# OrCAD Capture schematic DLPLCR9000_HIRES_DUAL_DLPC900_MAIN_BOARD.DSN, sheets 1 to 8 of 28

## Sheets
1 P02-Import Notice
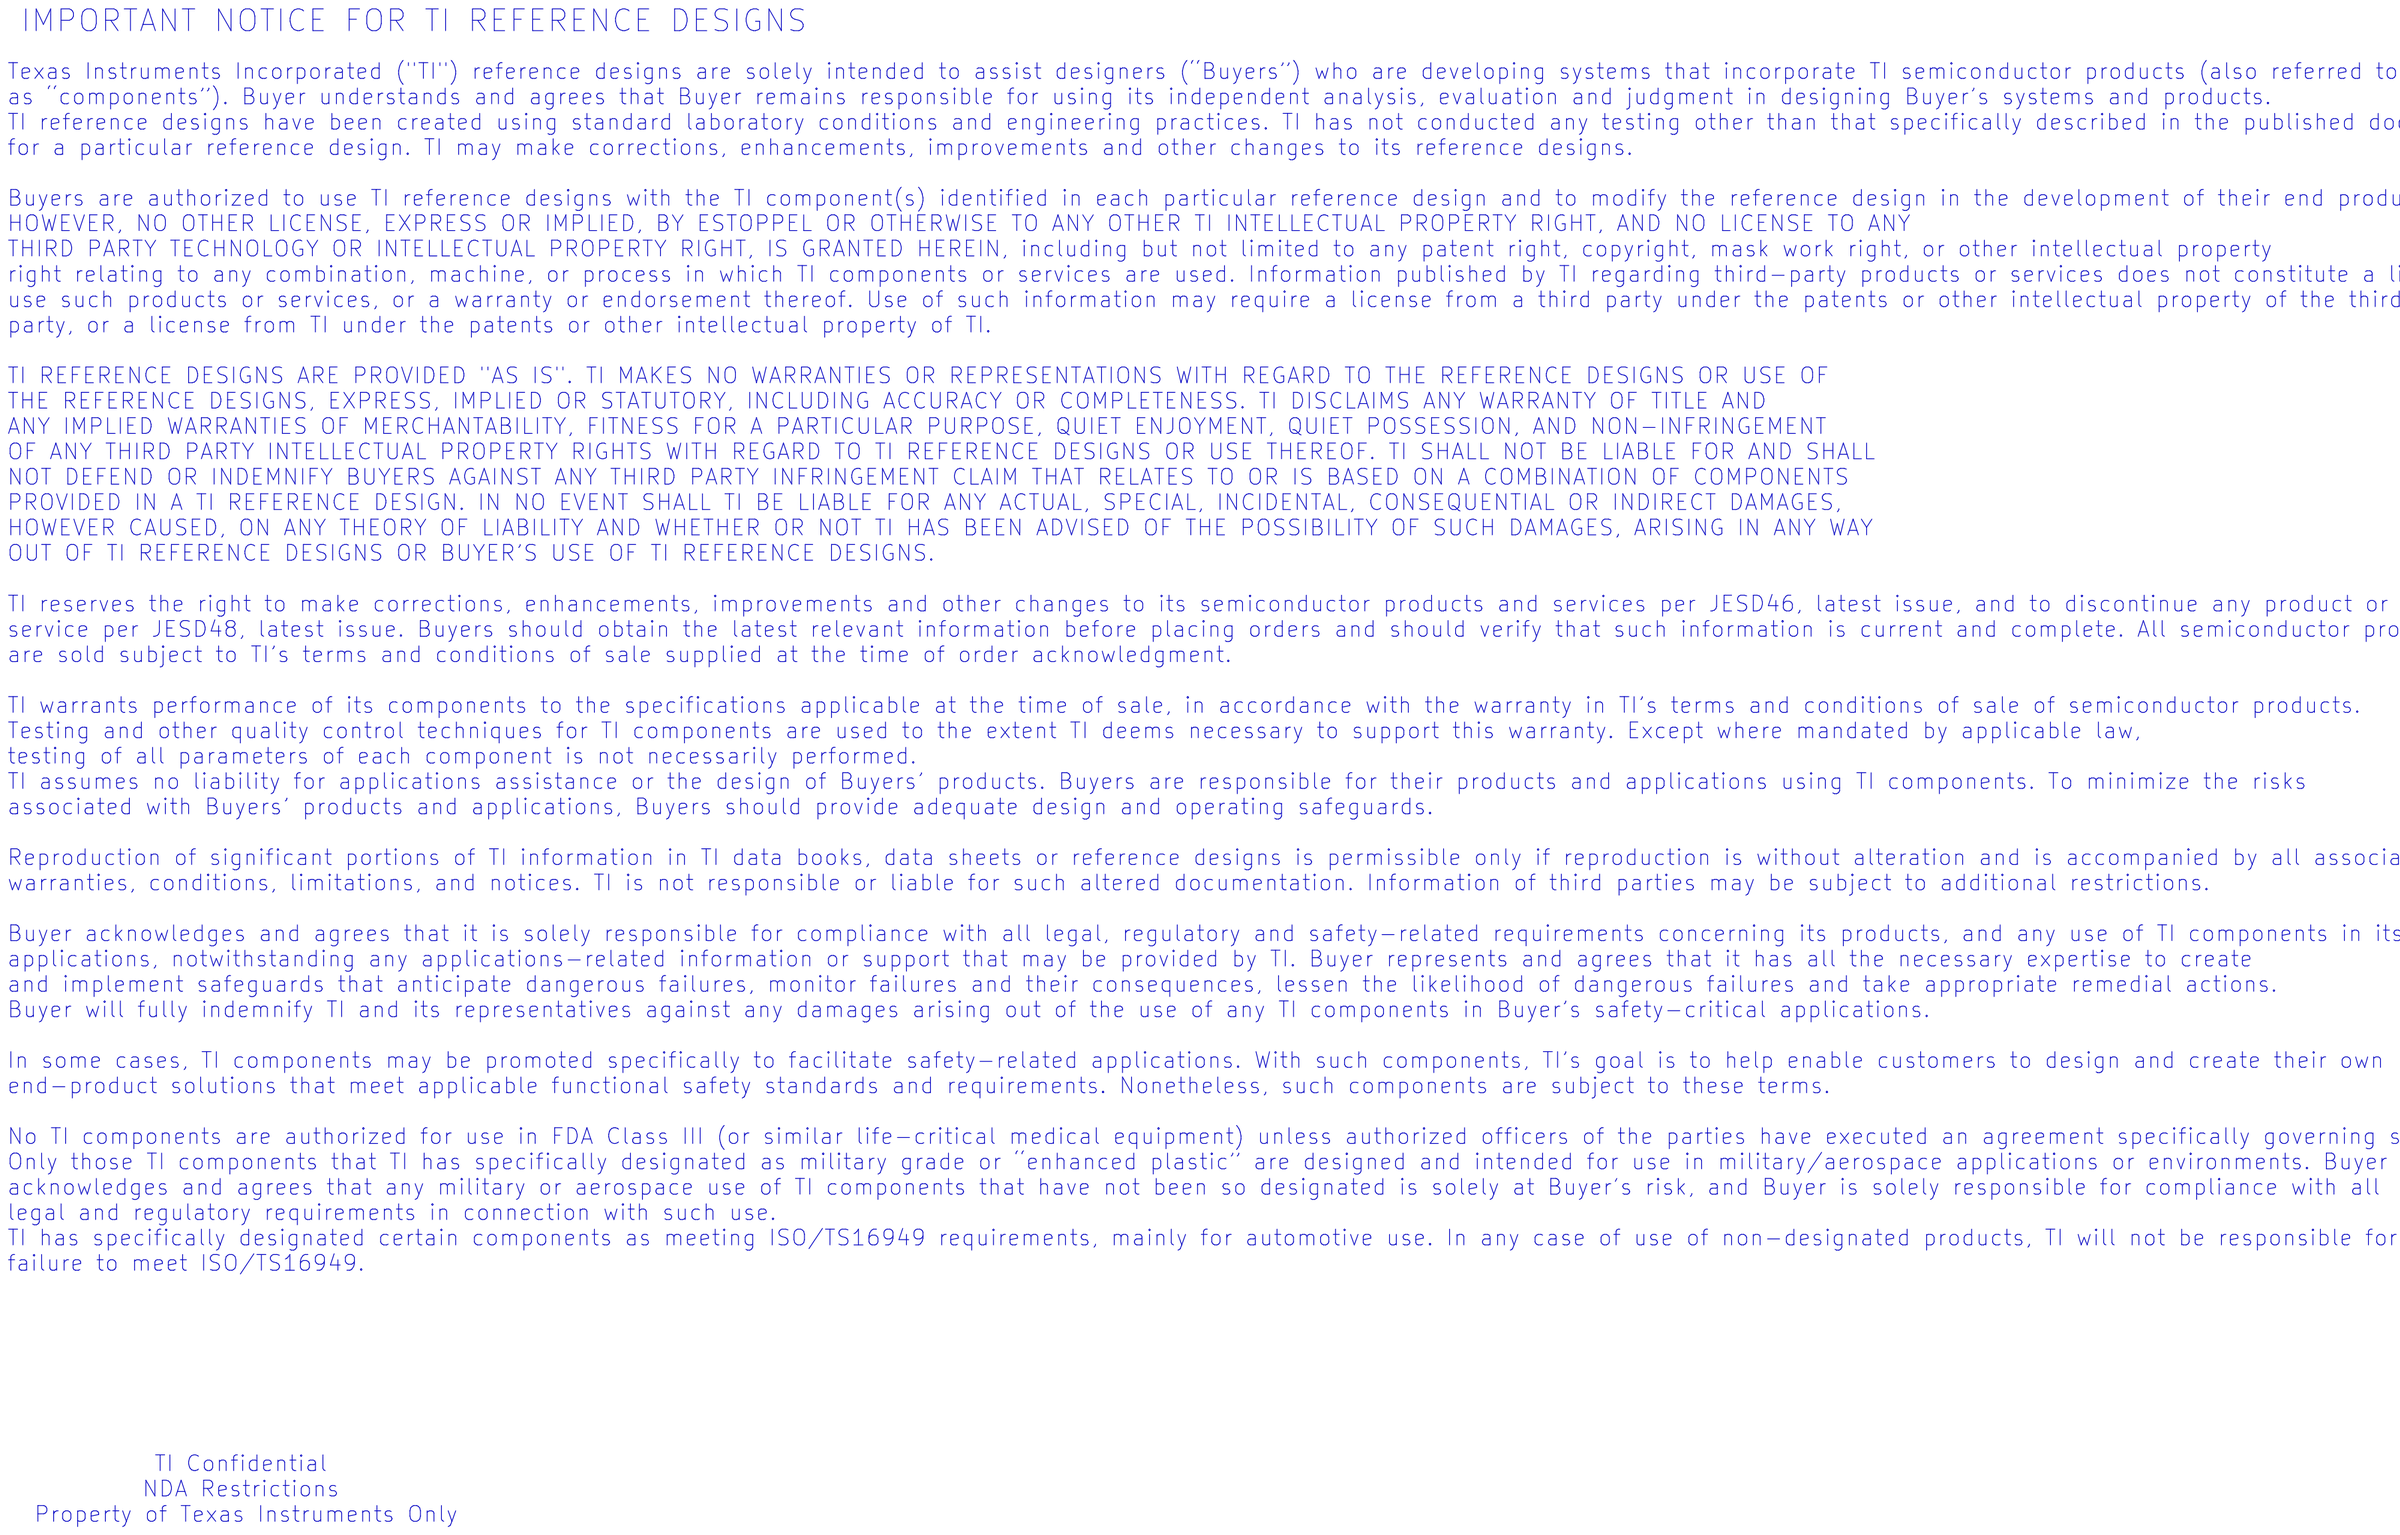
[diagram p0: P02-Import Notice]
2 P25-Power VCCIO & LDO: size A3
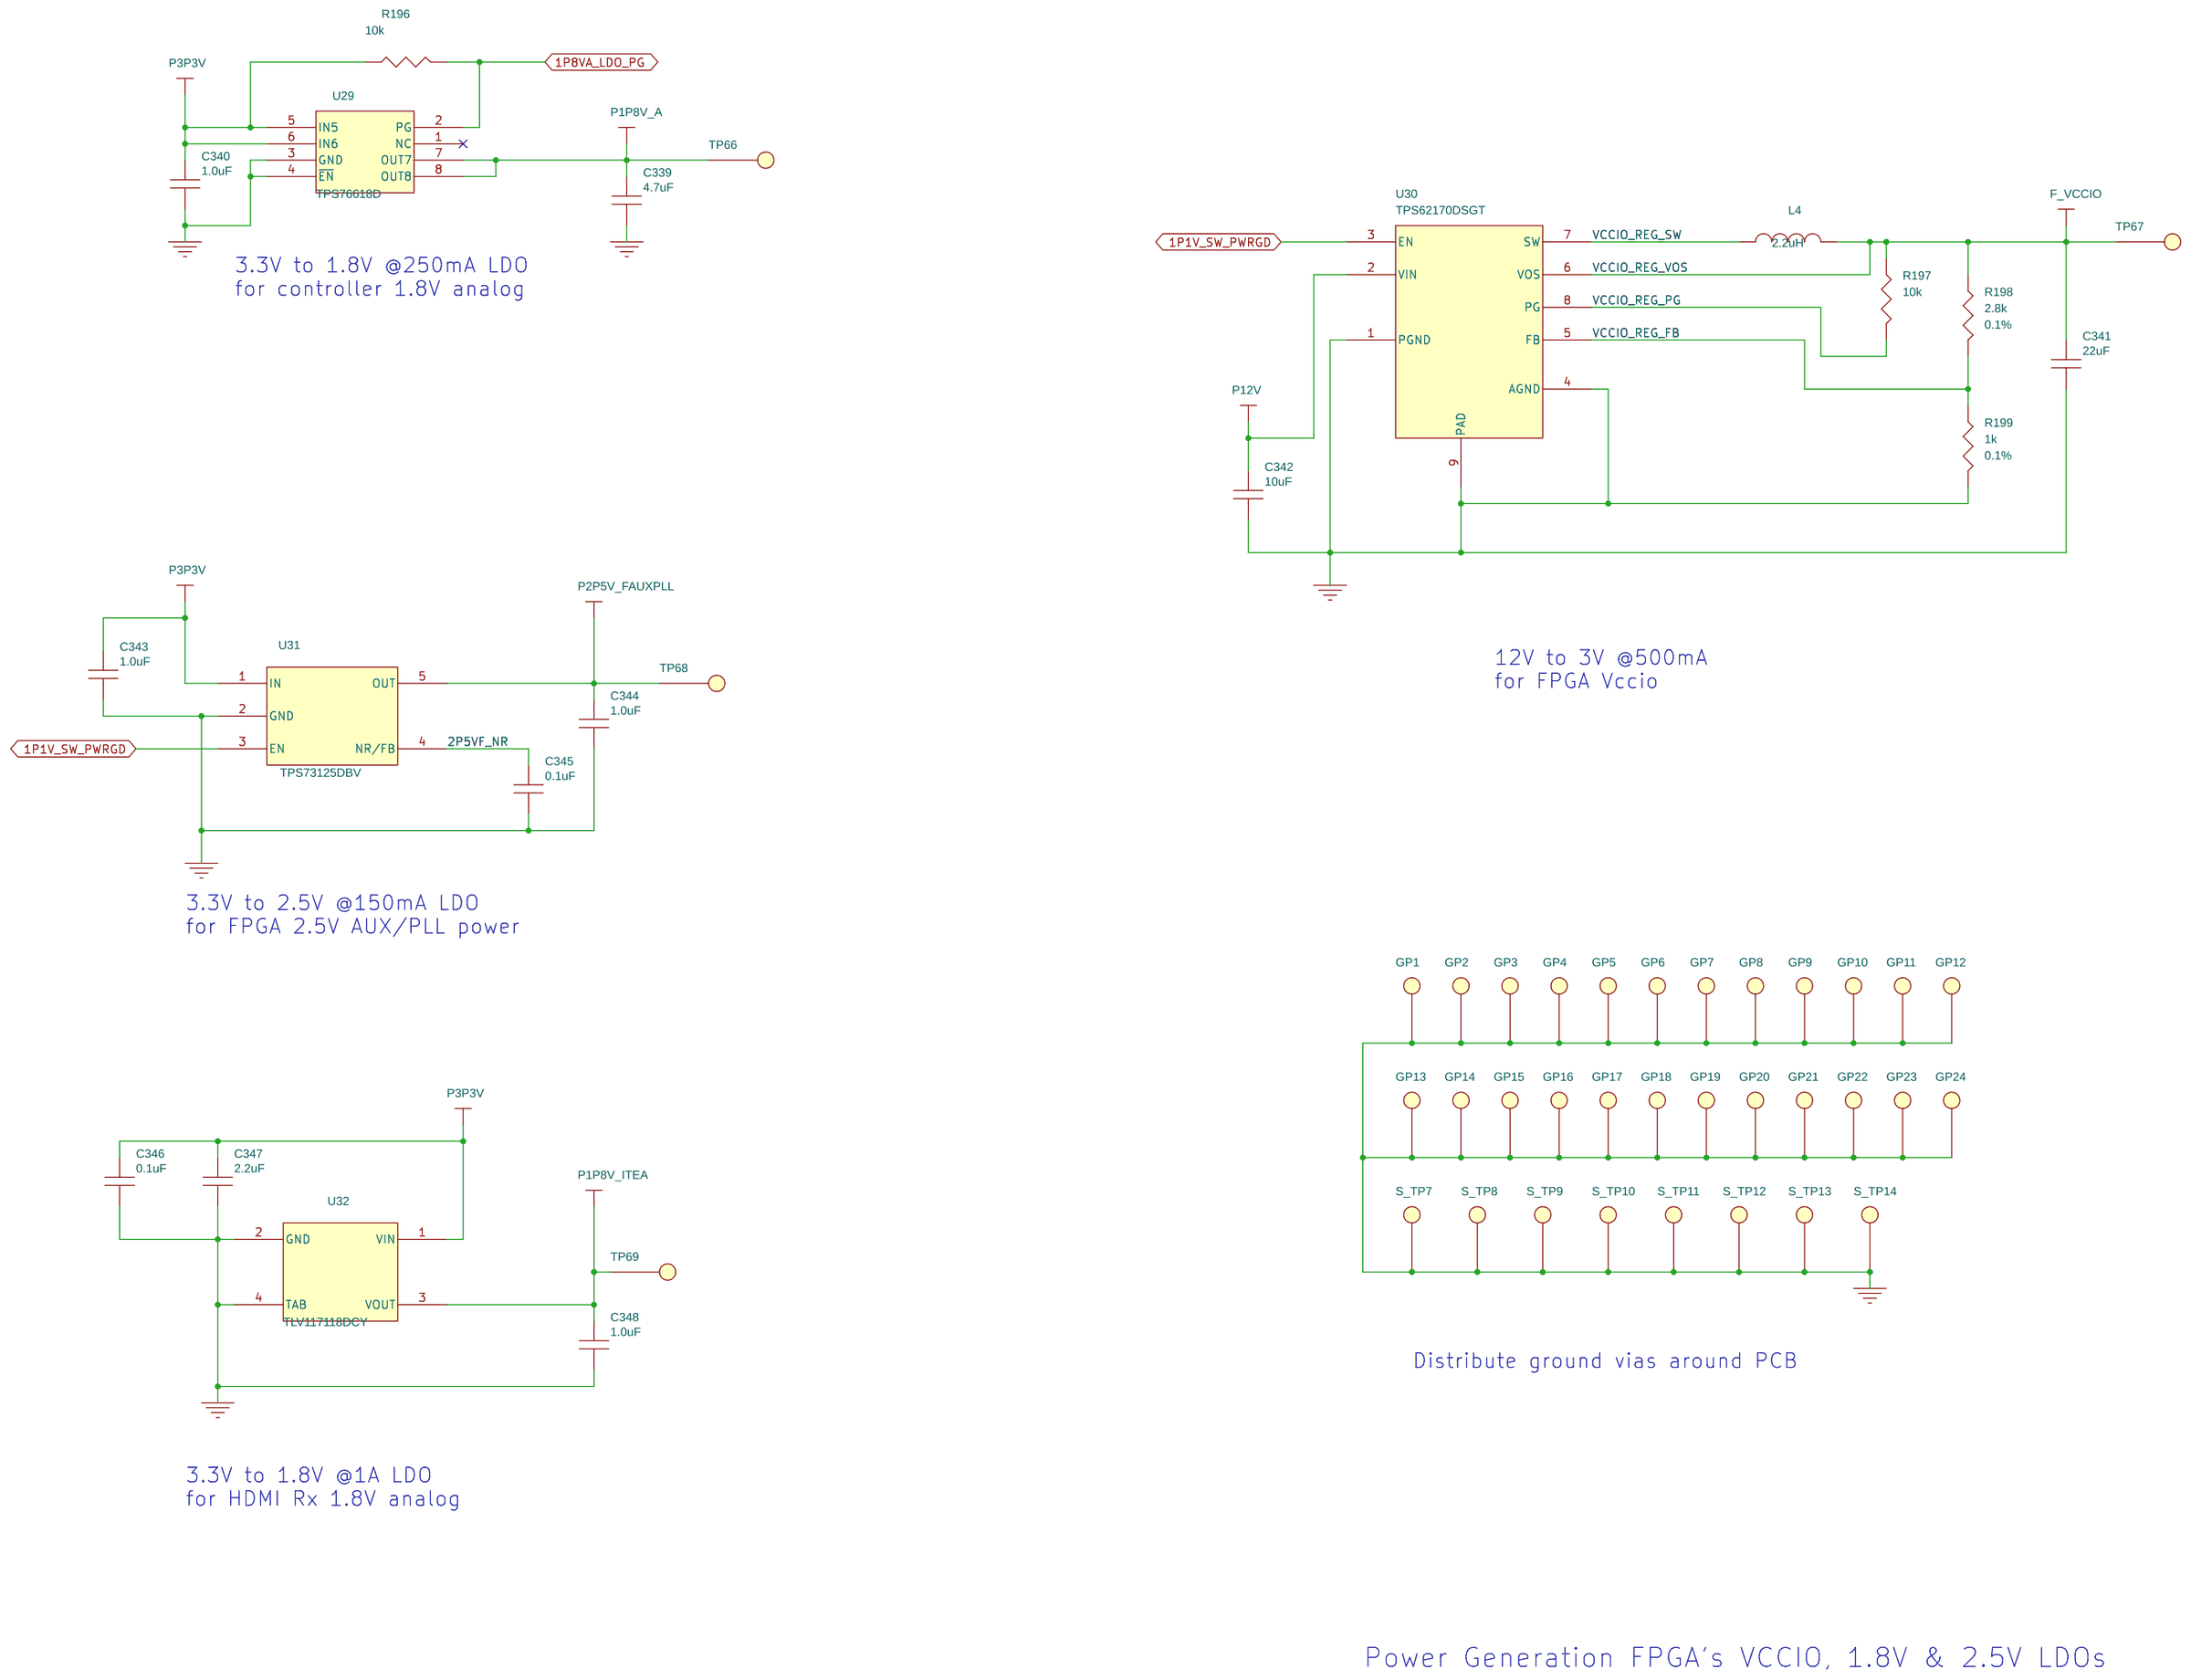
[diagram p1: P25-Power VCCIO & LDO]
3 P10-FPGA Config: size A3
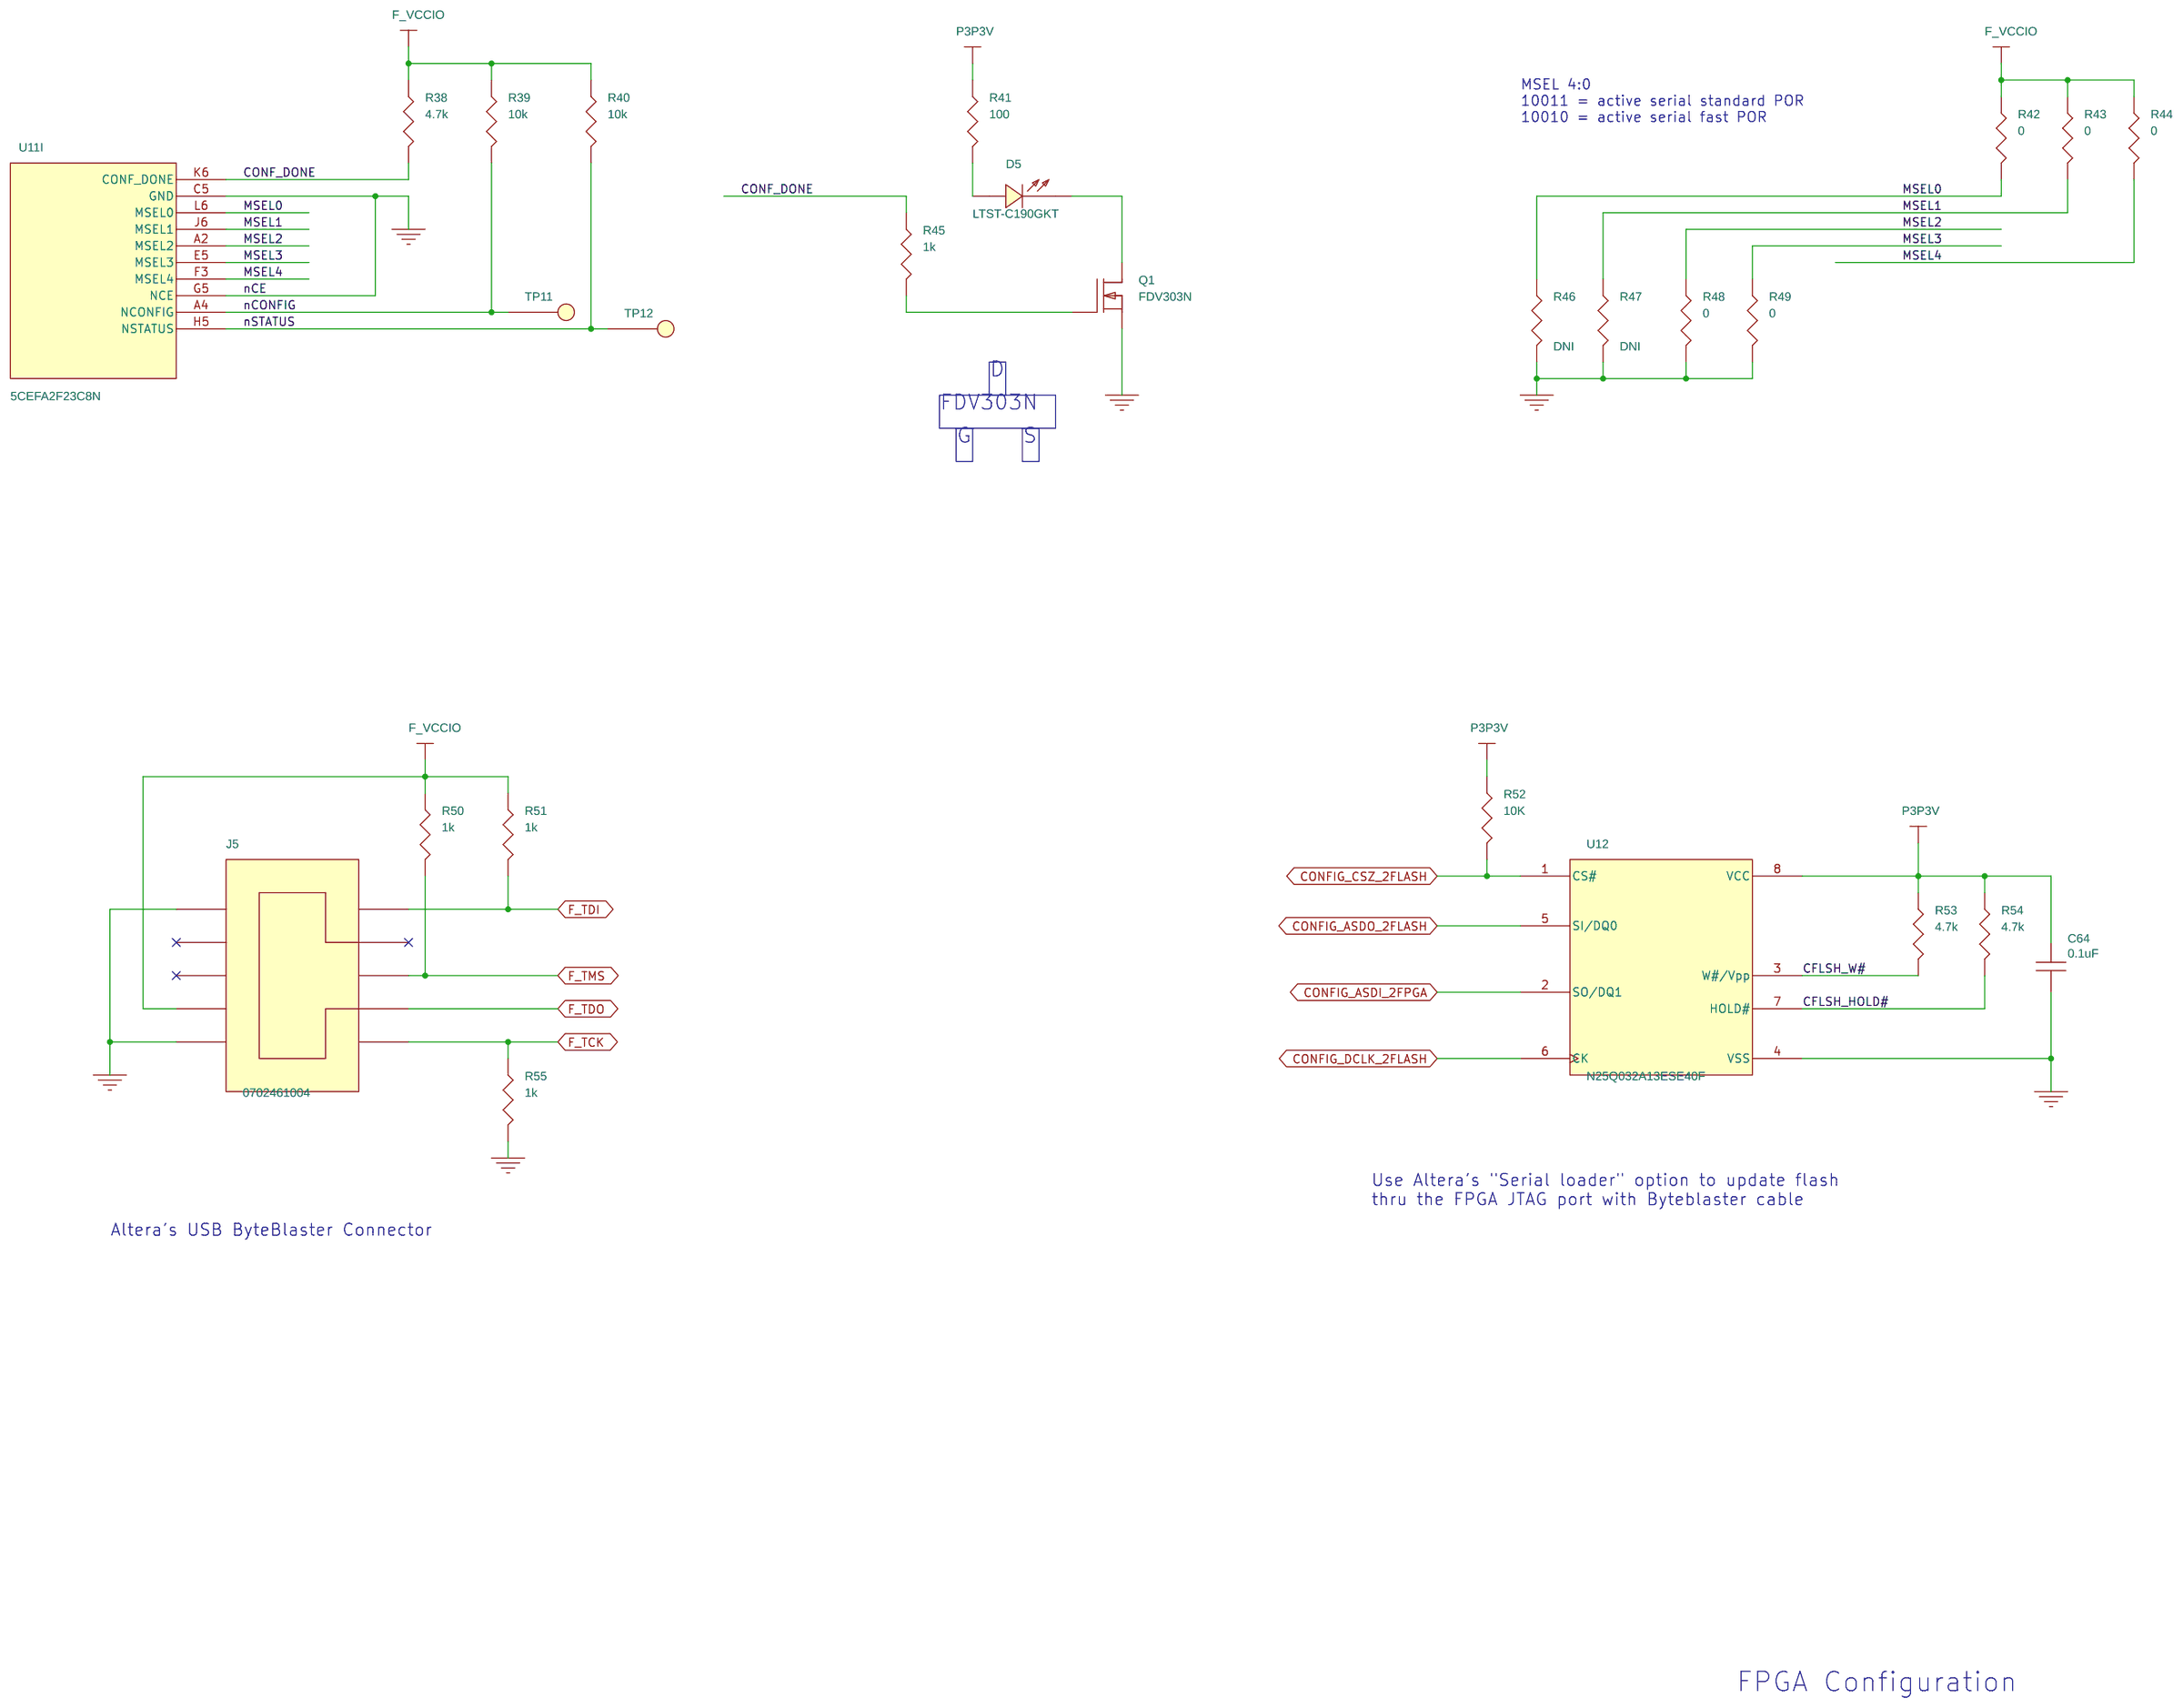
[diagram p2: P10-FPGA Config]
4 P09-FPGA Bank 5A,5B,7A,8A: size A3
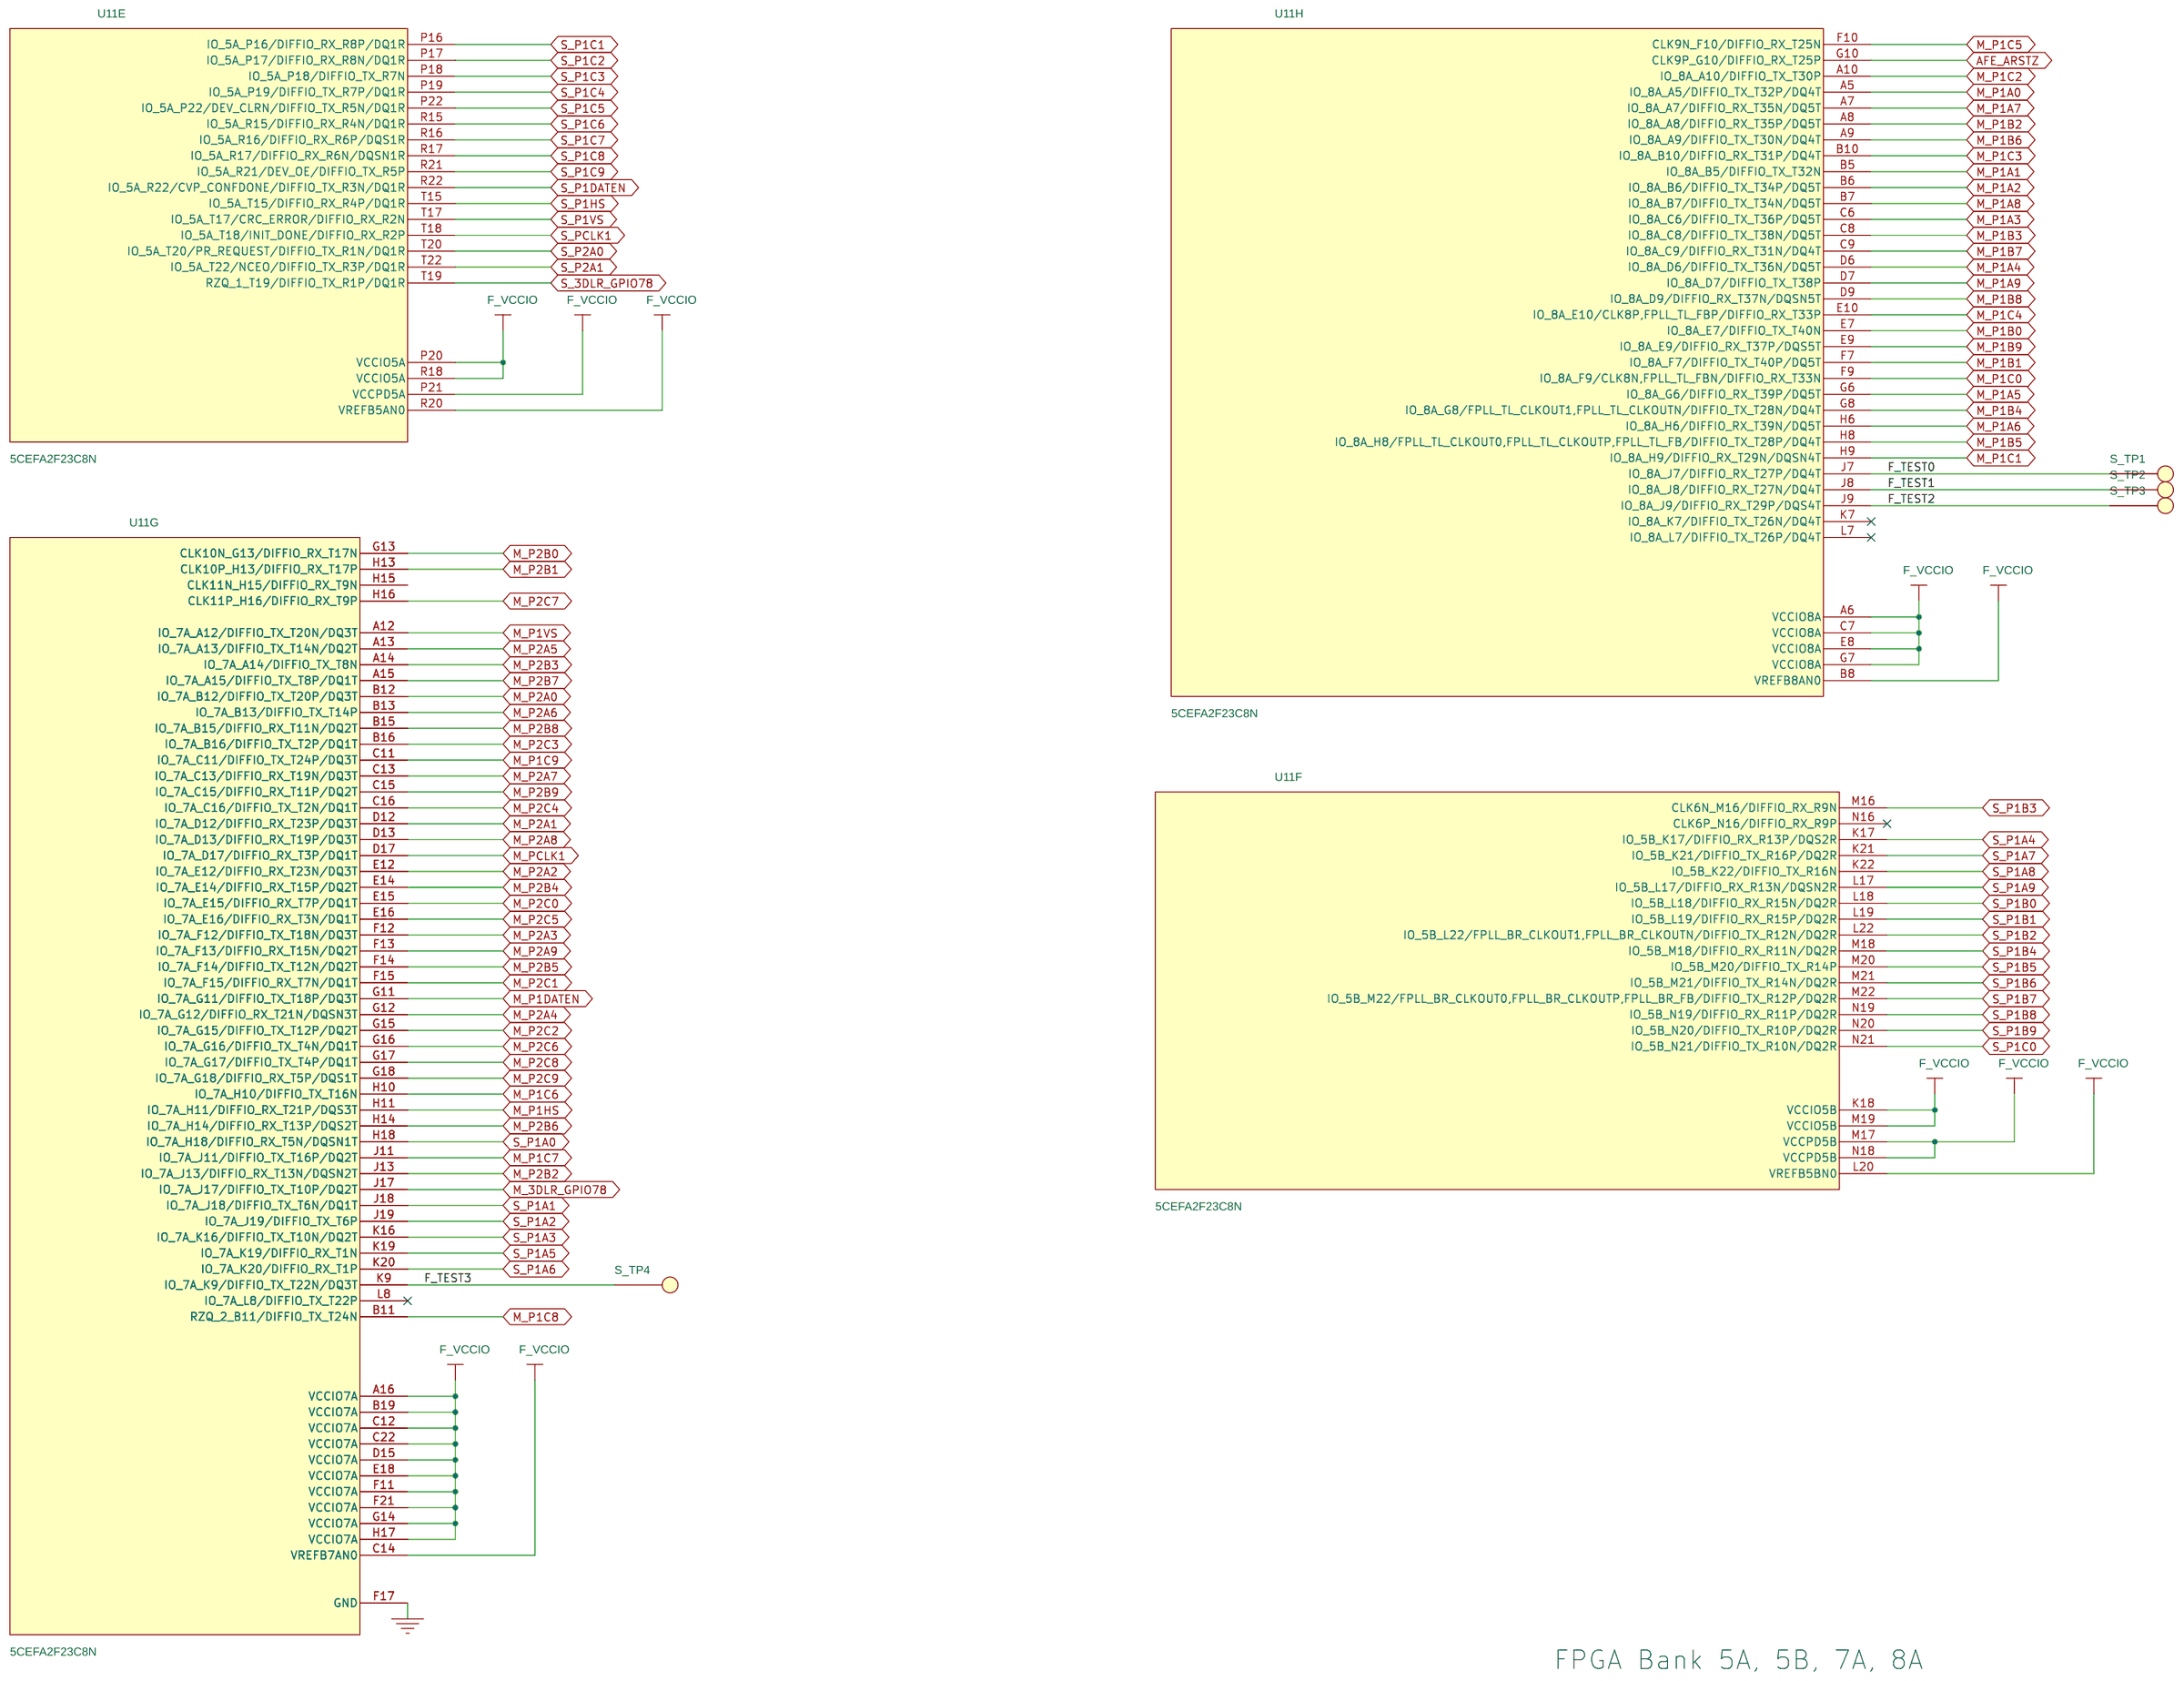
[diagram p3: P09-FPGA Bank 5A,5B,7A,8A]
5 P08-FPGA Bank 2A,3A,3B,4A: size A3
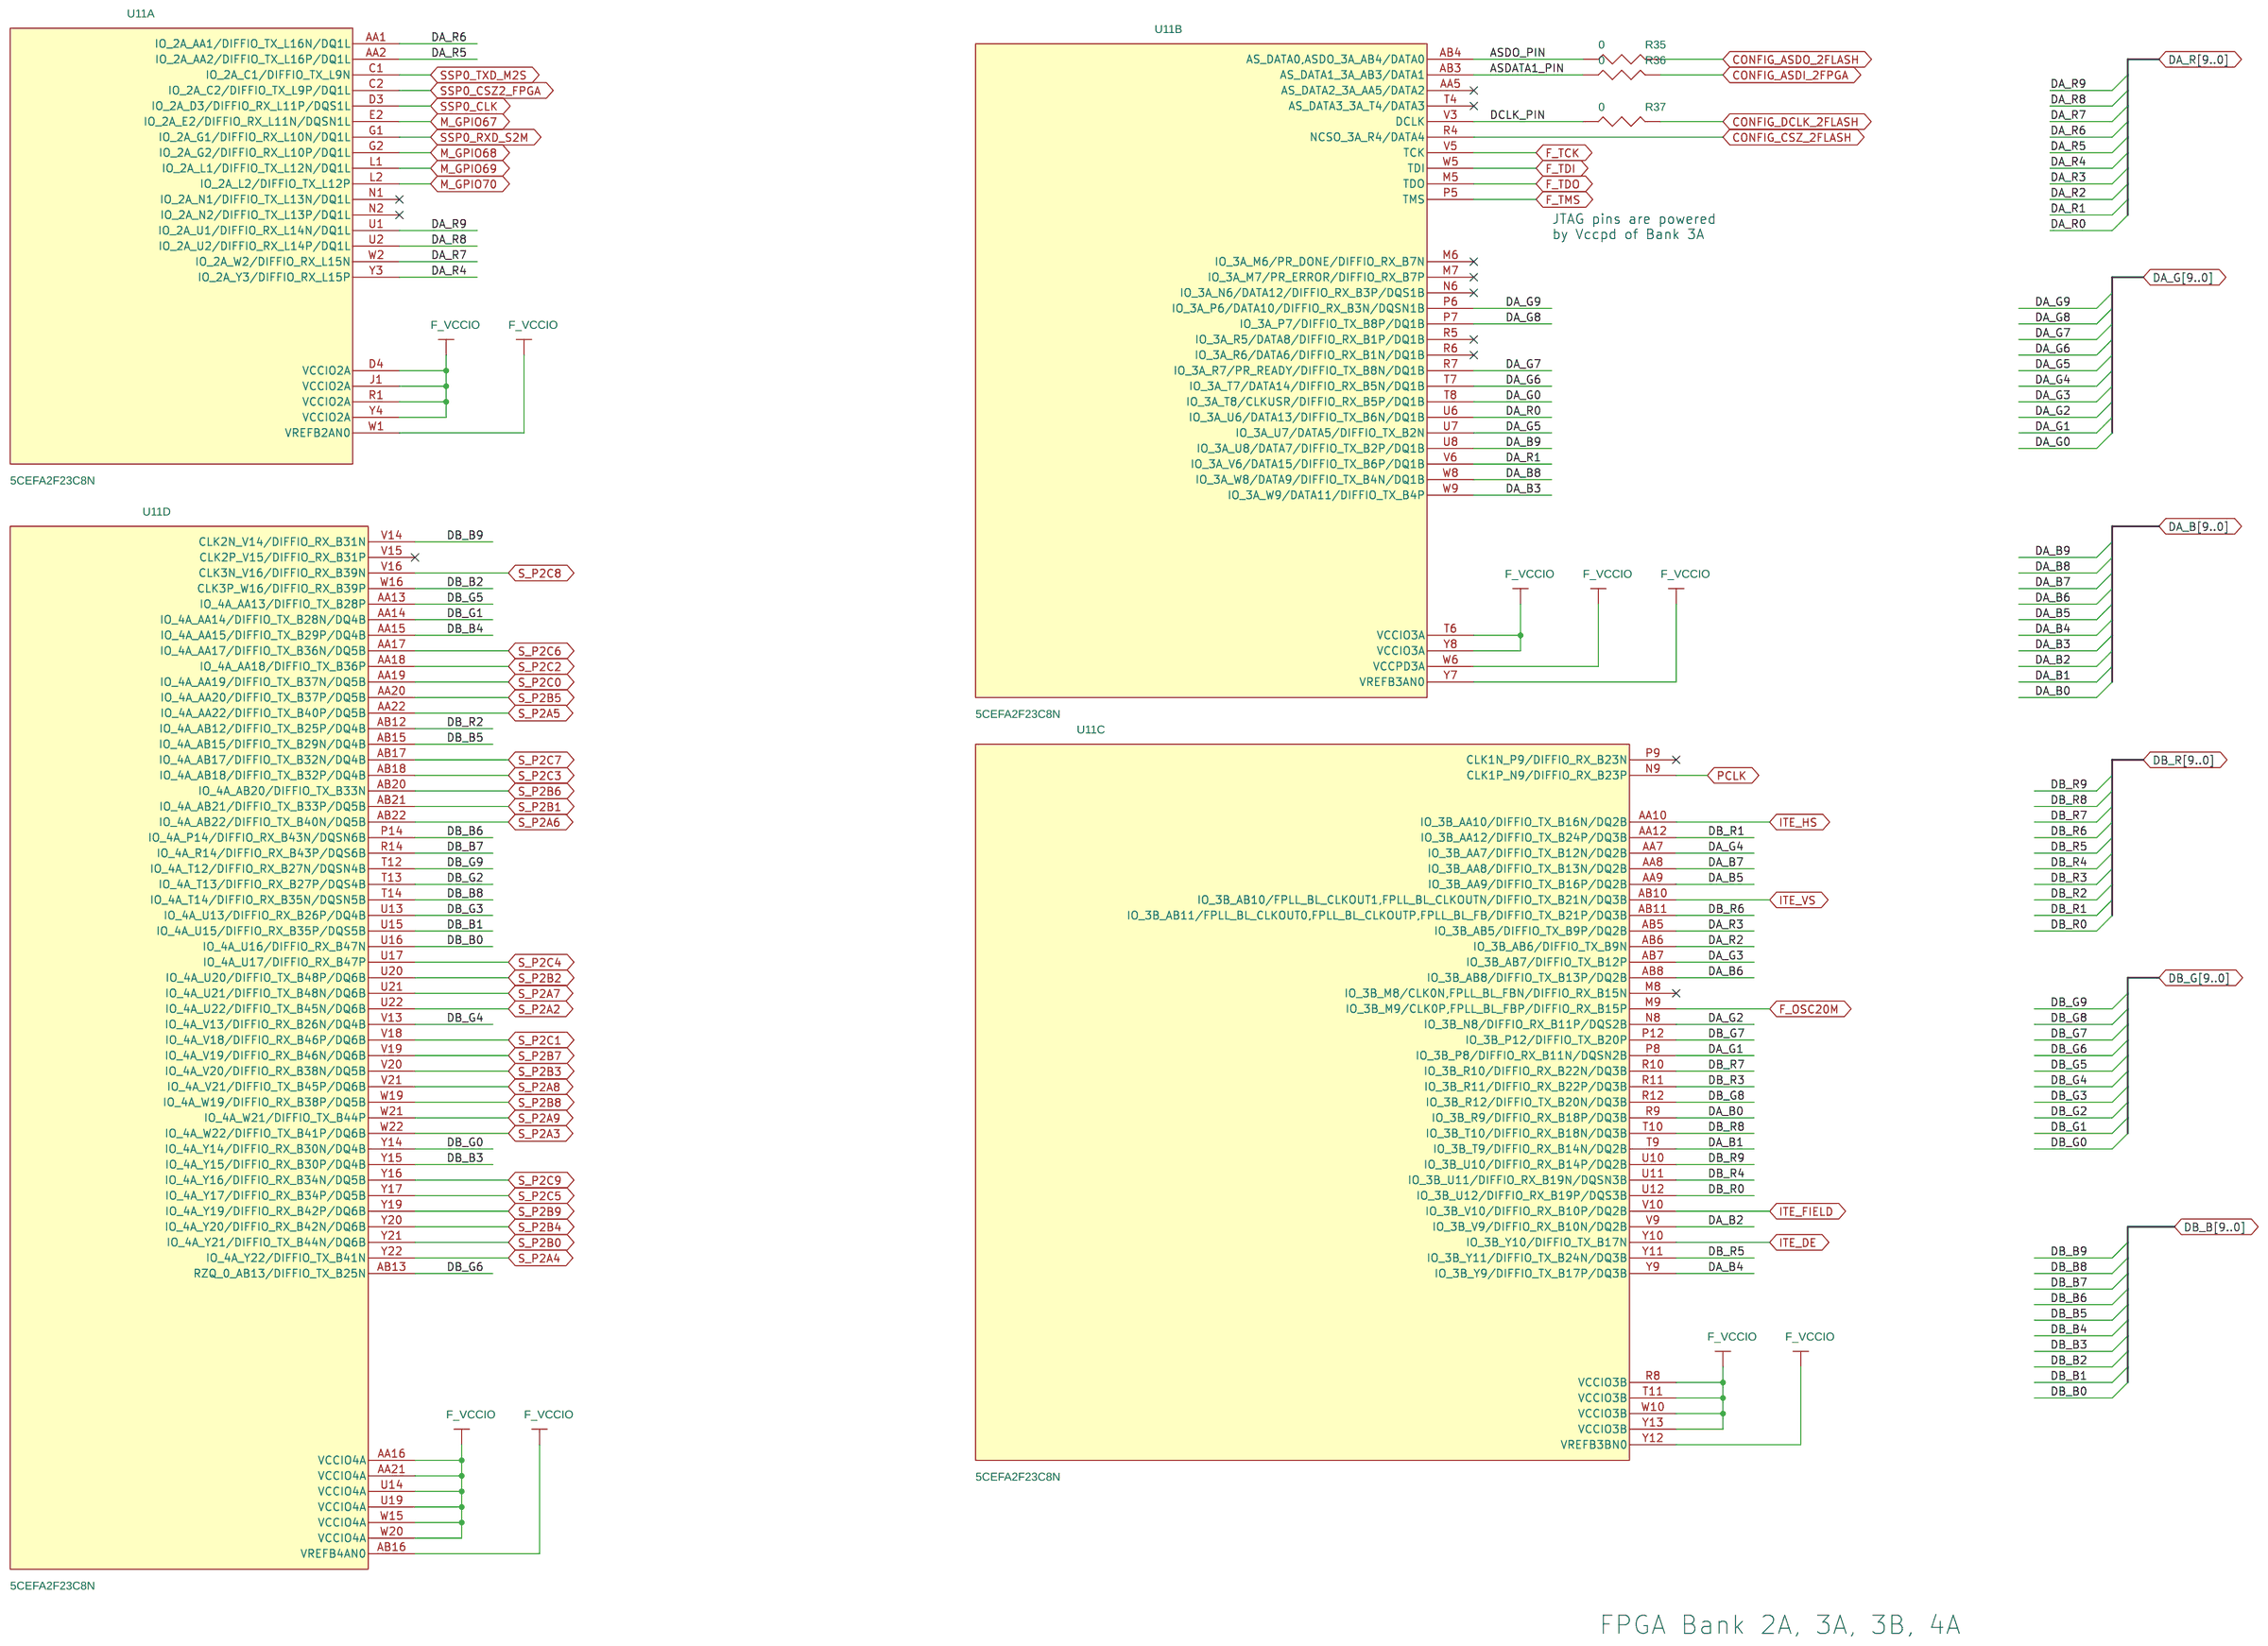
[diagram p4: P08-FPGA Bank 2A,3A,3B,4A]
6 P24-Power 1.1V, 1.8V, 3.3V: size A3
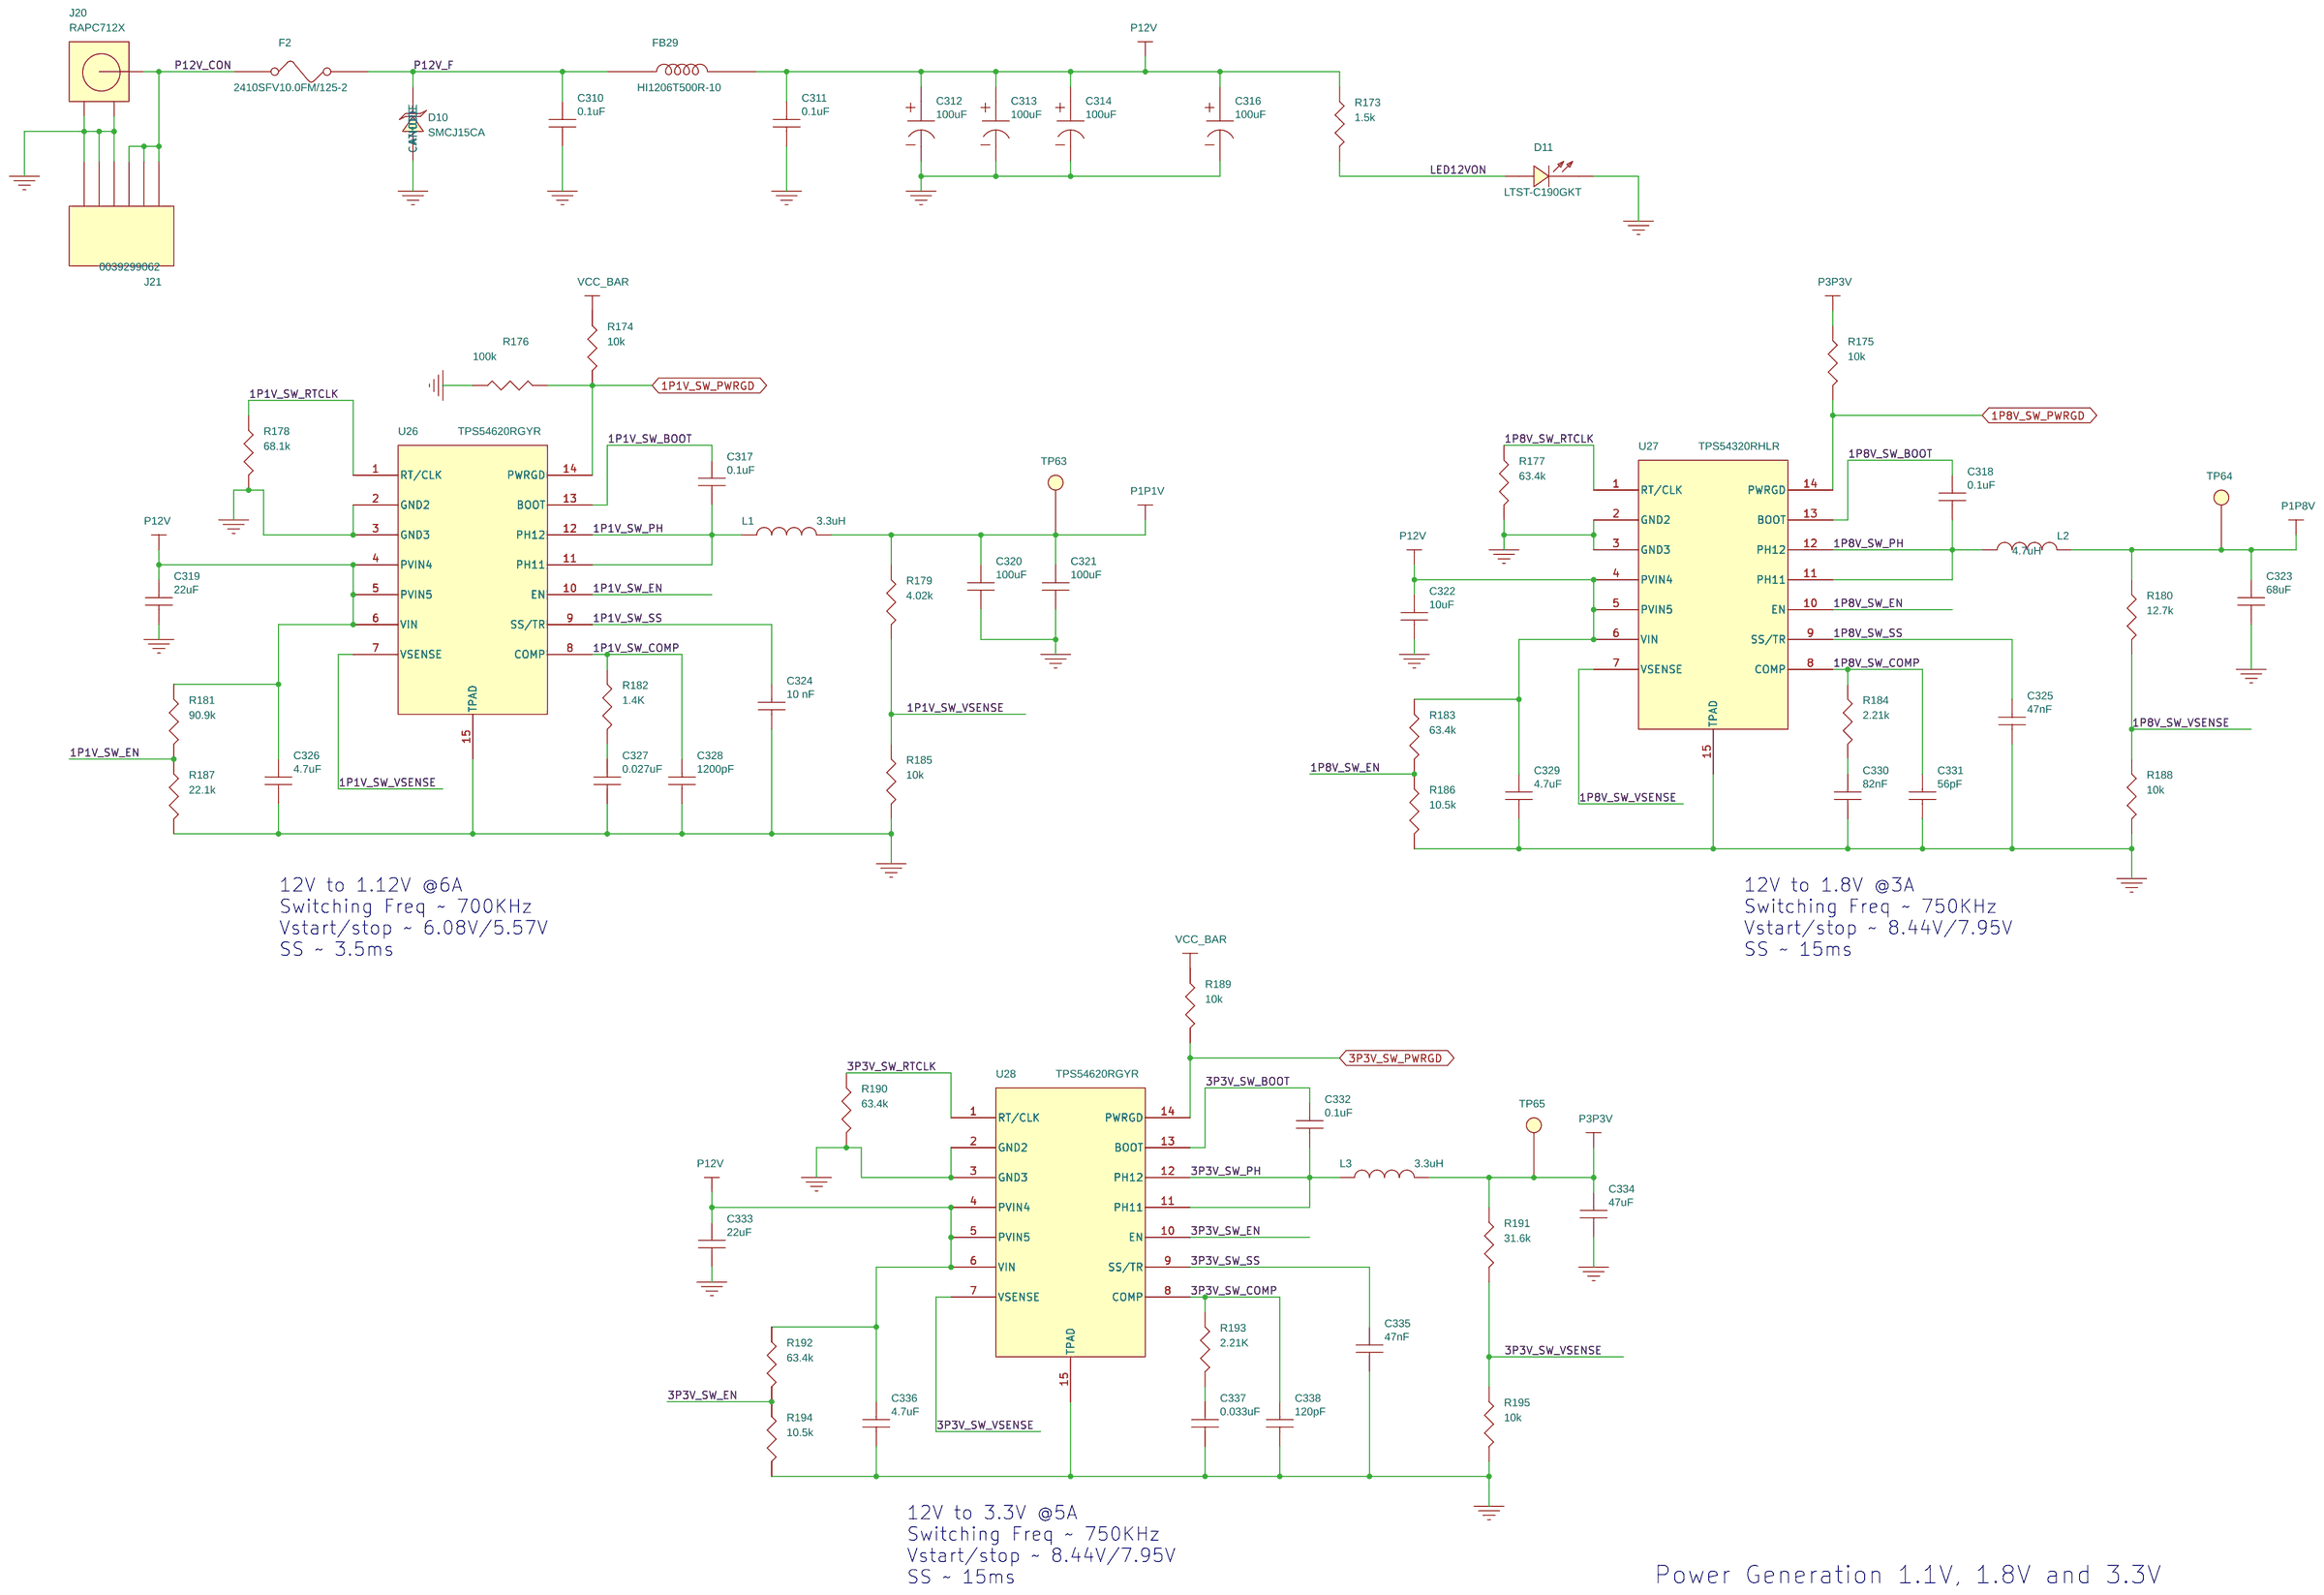
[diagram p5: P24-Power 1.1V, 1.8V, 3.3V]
7 P23-DMD Flex Connector: size A3
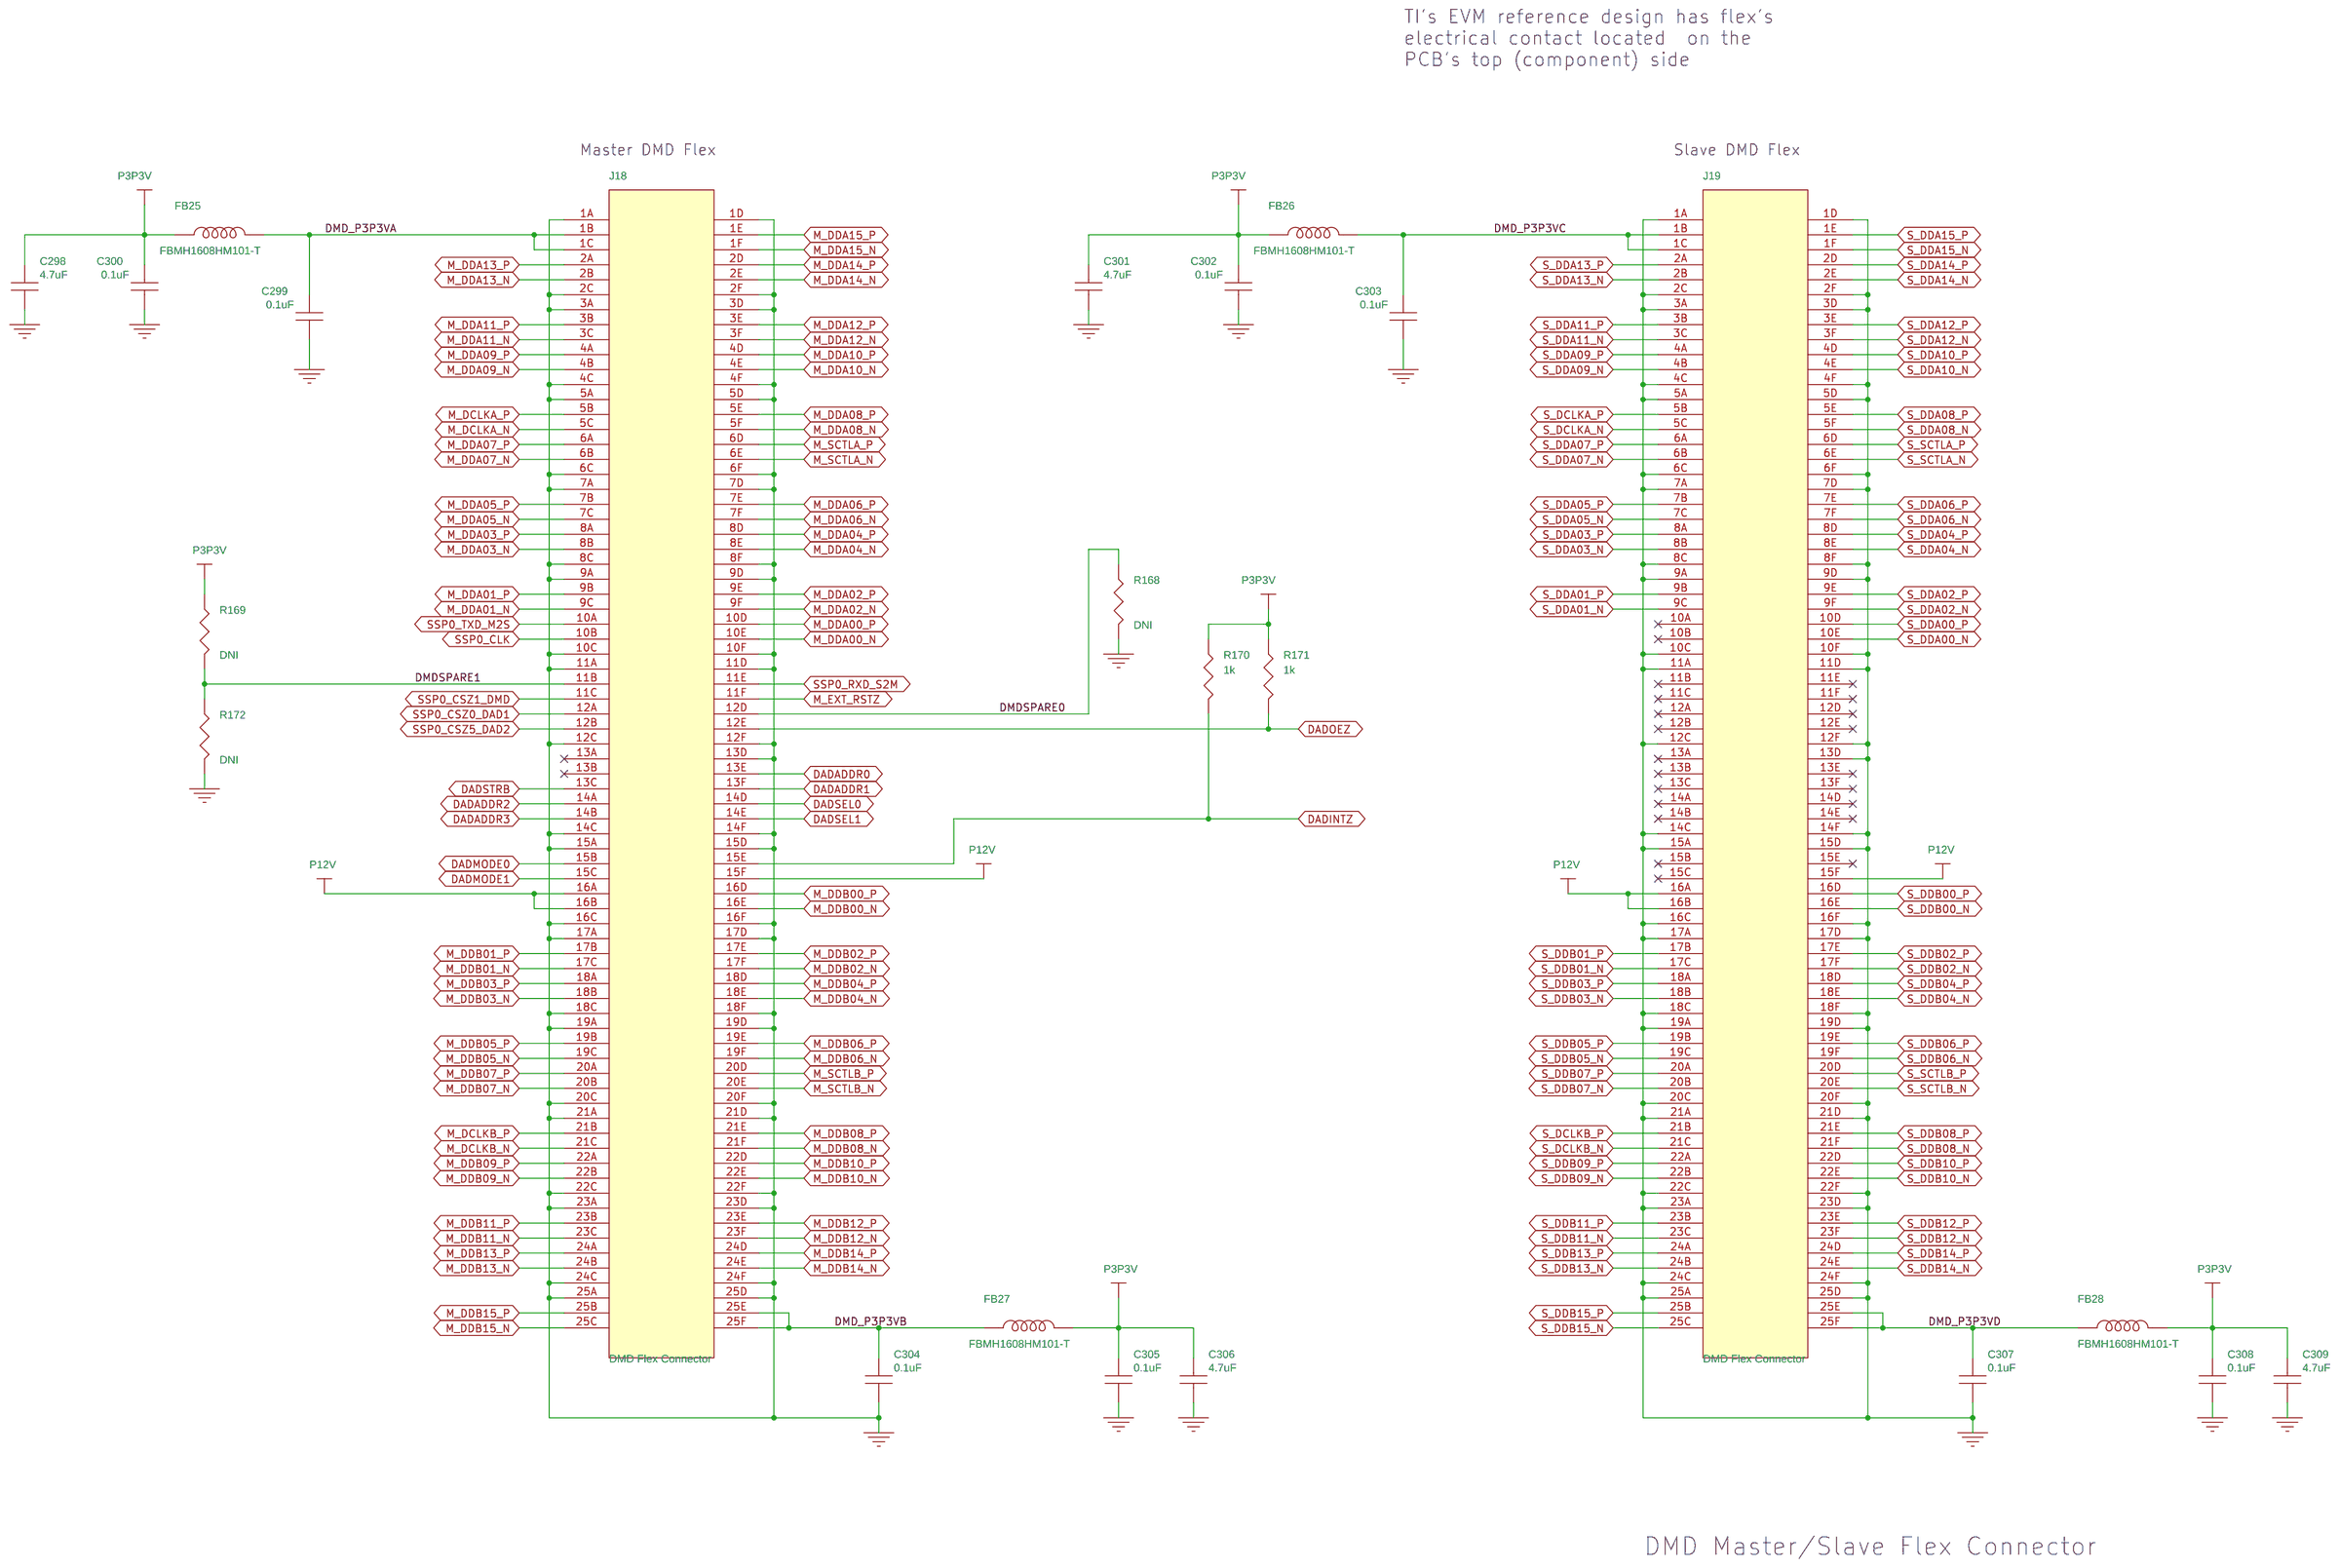
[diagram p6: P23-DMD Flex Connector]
8 P20-Slave Ext Flash Intf: size A3
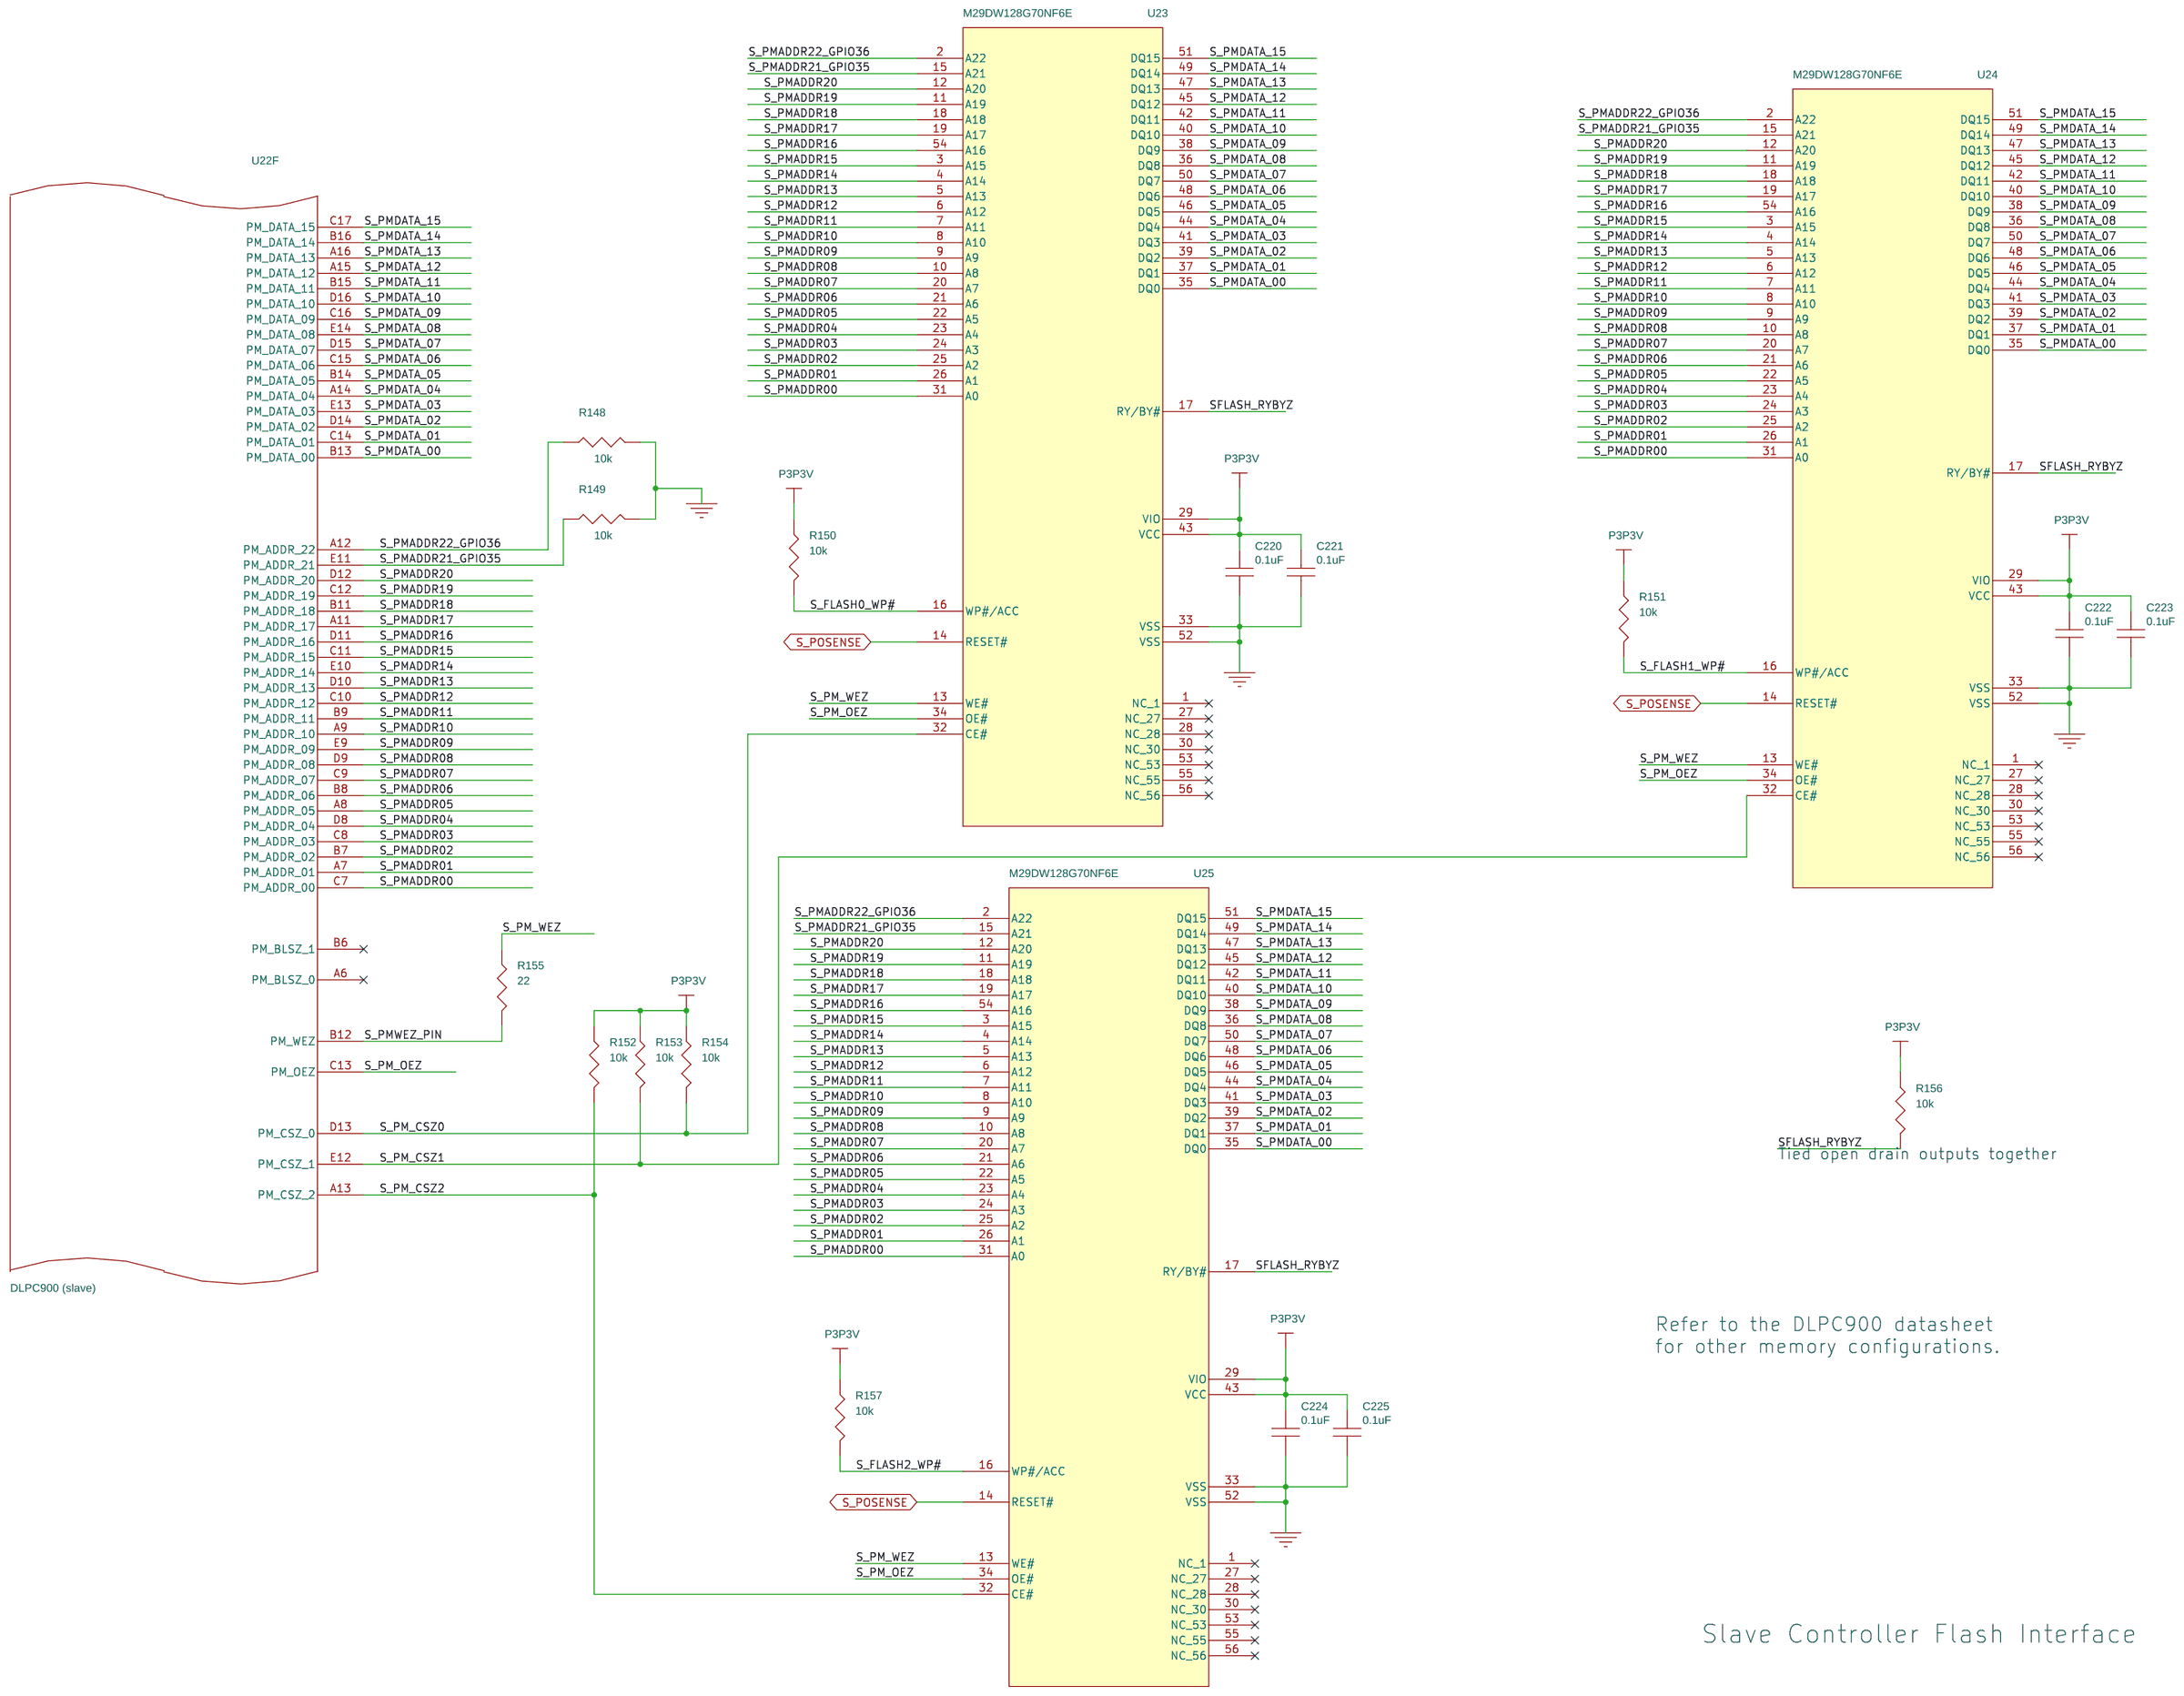
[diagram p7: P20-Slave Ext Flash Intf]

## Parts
sheet P08-FPGA Bank 2A,3A,3B,4A
R35  0  [0603]
R36  0  [0603]
R37  0  [0603]
U11  5CEFA2F23C8N  [F484]  (sections A,B,C,D,E,F,G,H,I,J,K)
sheet P09-FPGA Bank 5A,5B,7A,8A
S_TP1  SMD_Testpoint  [5015pad]
S_TP2  SMD_Testpoint  [5015pad]
S_TP3  SMD_Testpoint  [5015pad]
S_TP4  SMD_Testpoint  [5015pad]
sheet P10-FPGA Config
C64  0.1uF  [0402]
D5  LTST-C190GKT  [0603]
J5  0702461004  [10POS-2ROWS-2p54mm]
Q1  FDV303N  [SOT-23]
R38  4.7k  [0402]
R39  10k  [0402]
R40  10k  [0402]
R41  100  [0603]
R42  0  [0402]
R43  0  [0402]
R44  0  [0402]
R45  1k  [0603]
R46  DNI  [0402]
R47  DNI  [0402]
R48  0  [0402]
R49  0  [0402]
R50  1k  [0603]
R51  1k  [0603]
R52  10K  [0402]
R53  4.7k  [0402]
R54  4.7k  [0402]
R55  1k  [0603]
TP11  Testpoint  [24mil-plated]
TP12  Testpoint  [24mil-plated]
U12  N25Q032A13ESE40F  [SO8W]
sheet P20-Slave Ext Flash Intf
C220  0.1uF  [0402]
C221  0.1uF  [0402]
C222  0.1uF  [0402]
C223  0.1uF  [0402]
C224  0.1uF  [0402]
C225  0.1uF  [0402]
R148  10k  [0402]
R149  10k  [0402]
R150  10k  [0402]
R151  10k  [0402]
R152  10k  [0402]
R153  10k  [0402]
R154  10k  [0402]
R155  22  [0402]
R156  10k  [0402]
R157  10k  [0402]
U22  DLPC900 (slave)  [516BGA]  (sections A,B,C,D,E,F,G,H,I,J)
U23  M29DW128G70NF6E  [56TSOP]
U24  M29DW128G70NF6E  [56TSOP]
U25  M29DW128G70NF6E  [56TSOP]
sheet P23-DMD Flex Connector
C298  4.7uF  [0603]
C299  0.1uF  [0402]
C300  0.1uF  [0402]
C301  4.7uF  [0603]
C302  0.1uF  [0402]
C303  0.1uF  [0402]
C304  0.1uF  [0402]
C305  0.1uF  [0402]
C306  4.7uF  [0603]
C307  0.1uF  [0402]
C308  0.1uF  [0402]
C309  4.7uF  [0603]
FB25  FBMH1608HM101-T  [0603]
FB26  FBMH1608HM101-T  [0603]
FB27  FBMH1608HM101-T  [0603]
FB28  FBMH1608HM101-T  [0603]
J18  DMD Flex Connector  [150pins]
J19  DMD Flex Connector  [150pins]
R168  DNI  [0603]
R169  DNI  [0603]
R170  1k  [0603]
R171  1k  [0603]
R172  DNI  [0603]
sheet P24-Power 1.1V, 1.8V, 3.3V
C310  0.1uF  [0402]
C311  0.1uF  [0402]
C312  100uF  [2312]
C313  100uF  [2312]
C314  100uF  [2312]
C316  100uF  [2312]
C317  0.1uF  [0402]
C318  0.1uF  [0402]
C319  22uF  [1206]
C320  100uF  [1206]
C321  100uF  [1206]
C322  10uF  [0805]
C323  68uF  [1206]
C324  10 nF  [4002]
C325  47nF  [0402]
C326  4.7uF  [0805]
C327  0.027uF  [0402]
C328  1200pF  [0402]
C329  4.7uF  [0805]
C330  82nF  [0603]
C331  56pF  [0402]
C332  0.1uF  [0402]
C333  22uF  [1206]
C334  47uF  [1210]
C335  47nF  [0402]
C336  4.7uF  [0805]
C337  0.033uF  [0402]
C338  120pF  [0402]
D10  SMCJ15CA  [PN_DIODE]
D11  LTST-C190GKT  [0603]
F2  2410SFV10.0FM/125-2  [2410]
FB29  HI1206T500R-10  [1206]
J20  RAPC712X  [PAPC712Xthruhole]
J21  0039299062  [2x3_4p2mm_thruhole]
L1  3.3uH  [5x5mm]
L2  4.7uH  [4x4mm]
L3  3.3uH  [4x4mm]
R173  1.5k  [0603]
R174  10k  [0402]
R175  10k  [0603]
R176  100k  [0603]
R177  63.4k  [0402]
R178  68.1k  [0402]
R179  4.02k  [0402]
R180  12.7k  [0603]
R181  90.9k  [0402]
R182  1.4K  [0603]
R183  63.4k  [0402]
R184  2.21k  [0402]
R185  10k  [0402]
R186  10.5k  [0402]
R187  22.1k  [0402]
R188  10k  [0402]
R189  10k  [0402]
R190  63.4k  [0402]
R191  31.6k  [0402]
R192  63.4k  [0402]
R193  2.21K  [0402]
R194  10.5k  [0402]
R195  10k  [0402]
TP63  Testpoint  [24mil-plated]
TP64  Testpoint  [24mil-plated]
TP65  Testpoint  [24mil-plated]
U26  TPS54620RGYR  [14-VFQFN]
U27  TPS54320RHLR  [14-VFQFN]
U28  TPS54620RGYR  [14-VFQFN]
sheet P25-Power VCCIO & LDO
C339  4.7uF  [0603]
C340  1.0uF  [0402]
C341  22uF  [0805]
C342  10uF  [0805]
C343  1.0uF  [0402]
C344  1.0uF  [0402]
C345  0.1uF  [0402]
C346  0.1uF  [0402]
C347  2.2uF  [0603]
C348  1.0uF  [0402]
GP1  Ground point  [24mil-plated]
GP2  Ground point  [24mil-plated]
GP3  Ground point  [24mil-plated]
GP4  Ground point  [24mil-plated]
GP5  Ground point  [24mil-plated]
GP6  Ground point  [24mil-plated]
GP7  Ground point  [24mil-plated]
GP8  Ground point  [24mil-plated]
GP9  Ground point  [24mil-plated]
GP10  Ground point  [24mil-plated]
GP11  Ground point  [24mil-plated]
GP12  Ground point  [24mil-plated]
GP13  Ground point  [24mil-plated]
GP14  Ground point  [24mil-plated]
GP15  Ground point  [24mil-plated]
GP16  Ground point  [24mil-plated]
GP17  Ground point  [24mil-plated]
GP18  Ground point  [24mil-plated]
GP19  Ground point  [24mil-plated]
GP20  Ground point  [24mil-plated]
GP21  Ground point  [24mil-plated]
GP22  Ground point  [24mil-plated]
GP23  Ground point  [24mil-plated]
GP24  Ground point  [24mil-plated]
L4  2.2uH  [4x4mm]
R196  10k  [0603]
R197  10k  [0402]
R198  2.8k  [0402]
R199  1k  [0603]
S_TP7  SMD_Testpoint  [5015pad]
S_TP8  SMD_Testpoint  [5015pad]
S_TP9  SMD_Testpoint  [5015pad]
S_TP10  SMD_Testpoint  [5015pad]
S_TP11  SMD_Testpoint  [5015pad]
S_TP12  SMD_Testpoint  [5015pad]
S_TP13  SMD_Testpoint  [5015pad]
S_TP14  SMD_Testpoint  [5015pad]
TP66  Testpoint  [24mil-plated]
TP67  Testpoint  [24mil-plated]
TP68  Testpoint  [24mil-plated]
TP69  Testpoint  [24mil-plated]
U29  TPS76618D  [8SOIC]
U30  TPS62170DSGT  [8WSON]
U31  TPS73125DBV  [SOT23-5]
U32  TLV117118DCY  [SOT223]

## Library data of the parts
R35-R37 = 0.0_OHM_1_10W_0603
U11 = FPGA_Cyclone5_5CEFA2F23C8N
S_TP1-S_TP4 S_TP7-S_TP14 = SMD_Testpoint
C64 C220-C225 C299 C300 C302-C305 C307 C308 = CER_0.1UF_16V_10%_X5R_0402
D5 D11 = LED_GREEN_CLEAR_0603
J5 = 10POS_2ROWS_2.54MM_VERT
Q1 = FDV303N_MOSFET_N
R38 R53 R54 = 4.7K_OHM_1_10W_5%_0402
R39 R40 R46 R47 R52 R148-R154 R156 R157 R174 R189 R197 = 10K_OHM_1_10W_5%_0402
R41 = 100_OHM_1_10W_5%_0603
R42-R44 R48 R49 = 0.0_OHM_1_10W_0402
R45 R50 R51 R55 R168-R172 = 1.0K_OHM_1_16W_5%_0402
TP11 TP12 TP63-TP69 = Testpoint
U12 = Flash_N25Q_SPI_3.3V_32Mb_8SOW
R155 = 22_OHM_1_10W_1%_0402
U22 = DLPC900_910_datasheet
U23-U25 = NOR_Flash_128Mbits_3.3V_56TSOP
C298 C301 C306 C309 C339 = CER_4.7UF_16V_20%_X5R_0603
FB25-FB28 = FERRITE_BEAD_100_OHM_2A_0603
J18 J19 = DMD_FLEX_CONNECTOR: MFG Part Number: 8394-001
C310 C311 = CER_0.1UF_50V_10%_X7R_0402
C312-C314 C316 = TANT_100UF_25V_10%_2917
C317 C318 C332 C345 C346 = CER_0.1UF_25V_10%_X5R_0402
C319 C333 = CER_22UF_25V_10%_X5R_1206
C320 C321 = CER_100UF_6.3V_20%_X5R_1206
C322 C342 = CER_10UF_25V_10%_X5R_0805
C323 = CER_68UF_10V_20%_X5R_1206
C324 = CER_10_nF_25V_10%_X5R_0402
C325 C335 = CER_0.047UF_16V_10%_X7R_0402
C326 C329 C336 = CER_4.7UF_50V_10%_X5R_0805
C327 = CER_0.027UF_16V_10%_X5R_0402
C328 = CER_1200PF_50V_10%_X7R_0402
C330 = CER_0.082UF_50V_10%_X7R_0603
C331 = CER_56PF_50V_5%_NPO_0402
C334 = CER_47UF_16V_20%_X5R_1210
C337 = CER_0.033UF_16V_10%_X7R_0402
C338 = CER_120PF_50V_5%_NP0_0402
D10 = DIODE_TVS
F2 = FUSE_10A_125V_FAST_2410
FB29 = HI1206T500R-10_6A_50_OHM_1206
J20 = CON_PWRJACK3_RAPC712
J21 = PWR_CONN_HEADER_6POS_4.2MM_VERT
L1 = INDUCTOR_3.3UH_8.7A_20%
L2 = INDUCTOR_4.7UH_4.5A_20%
L3 = INDUCTOR_3.3UH_5.5A_20%
R173 = 1.5K_OHM_1_10W_5%_0603
R175 R196 = 10K_OHM_1_10W_5%_0603
R176 = 100K_OHM_1_10W_1%_0603
R177 R183 R190 R192 = 63.4K_OHM_1_10W_1%_0402
R178 = 68.1K_OHM_1_10W_1%_0402
R179 = 4.02K_OHM_1_10W_.1%_0402
R180 = 12.7K_OHM_1_10W_.1%_0603
R181 = 90.9K_OHM_1_10W_1%_0402
R182 = 1.4K_OHM_1_10W_1%_0603
R184 R193 = 2.21K_OHM_1_10W_1%_0402
R185 R188 R195 = 10K_OHM_1_16W_.1%_0402
R186 R194 = 10.5K_OHM_1_10W_1%_0402
R187 = 22.1K_OHM_1_10W_1%_0402
R191 = 31.6K_OHM_1_16W_.1%_0402
U26 U28 = TPS54620
U27 = TPS54320
C340 C343 C344 C348 = CER_1.0UF_16V_10%_X5R_0402
C341 = CER_22UF_16V_10%_X5R_0805
C347 = CER_2.2UF_25V_10%_X5R_0603
GP1-GP24 = Ground_point
L4 = INDUCTOR_2.2UH_XFL4020
R198 = 2.8K_OHM_1_16W_.1%_0402: Tolerance: 0.1%
R199 = 1.0K_OHM_1_10W_.1%_0603: Tolerance: 0.1%
U29 = TPS76618_REG_LDO_1.8V_0.25A
U30 = TPS62170_BUCK_SYNC_ADJ_0.5A
U31 = TPS73125DBV_LDO_2.5V_0.15A
U32 = TLV117118DCY_LDO_1.8V_1A_SOT223

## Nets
GND: C64.2 C220.2 C221.2 C222.2 C223.2 C224.2 C225.2 C298.2 C299.2 C300.2 C301.2 C302.2 C303.2 C304.2 C305.2 C306.2 C307.2 C308.2 C309.2 C310.2 C311.2 C312.2 C313.2 C314.2 C316.2 C319.2 C320.2 C321.2 C322.2 C323.2 C324.2 C325.2 C326.2 C327.2 C328.2 C329.2 C330.2 C331.2 C333.2 C334.2 C335.2 C336.2 C337.2 C338.2 C339.2 C340.2 C341.2 C342.2 C343.2 C344.2 C345.2 C346.2 C347.2 C348.2 D10.2(ANODE) D11.1(CATHODE) GP1.1 GP2.1 GP3.1 GP4.1 GP5.1 GP6.1 GP7.1 GP8.1 GP9.1 GP10.1 GP11.1 GP12.1 GP13.1 GP14.1 GP15.1 GP16.1 GP17.1 GP18.1 GP19.1 GP20.1 GP21.1 GP22.1 GP23.1 GP24.1 J5.2 J5.10 J18.1A J18.1D J18.2C J18.2F J18.3A J18.3D J18.4C J18.4F J18.5A J18.5D J18.6C J18.6F J18.7A J18.7D J18.8C J18.8F J18.9A J18.9D J18.10C J18.10F J18.11A J18.11D J18.12C J18.12F J18.13D J18.14C J18.14F J18.15A J18.15D J18.16C J18.16F J18.17A J18.17D J18.18C J18.18F J18.19A J18.19D J18.20C J18.20F J18.21A J18.21D J18.22C J18.22F J18.23A J18.23D J18.24C J18.24F J18.25A J18.25D J19.1A J19.1D J19.2C J19.2F J19.3A J19.3D J19.4C J19.4F J19.5A J19.5D J19.6C J19.6F J19.7A J19.7D J19.8C J19.8F J19.9A J19.9D J19.10C J19.10F J19.11A J19.11D J19.12C J19.12F J19.13D J19.14C J19.14F J19.15A J19.15D J19.16C J19.16F J19.17A J19.17D J19.18C J19.18F J19.19A J19.19D J19.20C J19.20F J19.21A J19.21D J19.22C J19.22F J19.23A J19.23D J19.24C J19.24F J19.25A J19.25D J20.2 J20.3 J21.1 J21.2 J21.3 Q1.S R46.2 R47.2 R48.2 R49.2 R55.2 R148.2 R149.2 R168.2 R172.2 R176.1 R177.2 R178.2 R185.2 R186.2 R187.2 R188.2 R190.2 R194.2 R195.2 R199.2 S_TP7.1 S_TP8.1 S_TP9.1 S_TP10.1 S_TP11.1 S_TP12.1 S_TP13.1 S_TP14.1 U11.C5(GND) U11.F17(GND) U11.G5(NCE) U12.4(VSS) U23.33(VSS) U23.52(VSS) U24.33(VSS) U24.52(VSS) U25.33(VSS) U25.52(VSS) U26.2(GND2) U26.3(GND3) U26.15(TPAD) U27.2(GND2) U27.3(GND3) U27.15(TPAD) U28.2(GND2) U28.3(GND3) U28.15(TPAD) U29.3(GND) U29.4(~{EN}) U30.1(PGND) U30.4(AGND) U30.9(PAD) U31.2(GND) U32.2(GND) U32.4(TAB) ; also on sheet 9 10 12 13 14 15 16 17 18 22 24 25 26 27 28
P12V: C311.1 C312.1 C313.1 C314.1 C316.1 C319.1 C322.1 C326.1 C329.1 C333.1 C336.1 C342.1 FB29.2 J18.15F J18.16A J18.16B J19.15F J19.16A J19.16B R173.1 R181.1 R183.1 R192.1 U26.4(PVIN4) U26.5(PVIN5) U26.6(VIN) U27.4(PVIN4) U27.5(PVIN5) U27.6(VIN) U28.4(PVIN4) U28.5(PVIN5) U28.6(VIN) U30.2(VIN) ; also on sheet 12 13
P12V_CON: F2.1 J20.1 J21.4 J21.5 J21.6
P12V_F: C310.1 D10.1(CATHODE) F2.2 FB29.1
VCCIO_REG_FB: R198.2 R199.1 U30.5(FB)
VCCIO_REG_PG: R197.2 U30.8(PG)
VCCIO_REG_SW: L4.1 U30.7(SW)
1P1V_SW_BOOT: C317.1 U26.13(BOOT)
1P1V_SW_COMP: C328.1 R182.1 U26.8(COMP)
1P1V_SW_EN: R181.2 R187.1 U26.10(EN)
1P1V_SW_PH: C317.2 L1.1 U26.11(PH11) U26.12(PH12)
1P1V_SW_PWRGD: R174.2 R176.2 U26.14(PWRGD) U30.3(EN) U31.3(EN) ; also on sheet 13
1P1V_SW_RTCLK: R178.1 U26.1(RT/CLK)
1P1V_SW_SS: C324.1 U26.9(SS/TR)
1P1V_SW_VSENSE: R179.2 R185.1 U26.7(VSENSE)
1P8V_SW_BOOT: C318.1 U27.13(BOOT)
1P8V_SW_COMP: C331.1 R184.1 U27.8(COMP)
1P8V_SW_EN: R183.2 R186.1 U27.10(EN)
1P8V_SW_PH: C318.2 L2.1 U27.11(PH11) U27.12(PH12)
1P8V_SW_PWRGD: R175.2 U27.14(PWRGD) ; also on sheet 13
1P8V_SW_RTCLK: R177.1 U27.1(RT/CLK)
1P8V_SW_SS: C325.1 U27.9(SS/TR)
1P8V_SW_VSENSE: R180.2 R188.1 U27.7(VSENSE)
1P8VA_LDO_PG: R196.2 U29.2(PG) ; also on sheet 13
2P5VF_NR: C345.1 U31.4(NR/FB)
3P3V_SW_BOOT: C332.1 U28.13(BOOT)
3P3V_SW_COMP: C338.1 R193.1 U28.8(COMP)
3P3V_SW_EN: R192.2 R194.1 U28.10(EN)
3P3V_SW_PH: C332.2 L3.1 U28.11(PH11) U28.12(PH12)
3P3V_SW_PWRGD: R189.2 U28.14(PWRGD) ; also on sheet 13
3P3V_SW_RTCLK: R190.1 U28.1(RT/CLK)
3P3V_SW_SS: C335.1 U28.9(SS/TR)
3P3V_SW_VSENSE: R191.2 R195.1 U28.7(VSENSE)
AFE_ARSTZ: U11.G10(CLK9P_G10/DIFFIO_RX_T25P) ; also on sheet 18 22
ASDATA1_PIN: R36.1 U11.AB3(AS_DATA1_3A_AB3/DATA1)
ASDO_PIN: R35.1 U11.AB4(AS_DATA0,ASDO_3A_AB4/DATA0)
CFLSH_HOLD#: R54.2 U12.7(HOLD#)
CFLSH_W#: R53.2 U12.3(W#/Vpp)
CONF_DONE: R38.2 R45.1 U11.K6(CONF_DONE)
CONFIG_ASDI_2FPGA: R36.2 U12.2(SO/DQ1)
CONFIG_ASDO_2FLASH: R35.2 U12.5(SI/DQ0)
CONFIG_CSZ_2FLASH: R52.2 U11.R4(NCSO_3A_R4/DATA4) U12.1(CS#)
CONFIG_DCLK_2FLASH: R37.2 U12.6(CK)
DA_B0: U11.R9(IO_3B_R9/DIFFIO_RX_B18P/DQ3B) ; also on sheet 22
DA_B1: U11.T9(IO_3B_T9/DIFFIO_RX_B14N/DQ2B) ; also on sheet 22
DA_B2: U11.V9(IO_3B_V9/DIFFIO_RX_B10N/DQ2B) ; also on sheet 22
DA_B3: U11.W9(IO_3A_W9/DATA11/DIFFIO_TX_B4P) ; also on sheet 22
DA_B4: U11.Y9(IO_3B_Y9/DIFFIO_TX_B17P/DQ3B) ; also on sheet 22
DA_B5: U11.AA9(IO_3B_AA9/DIFFIO_TX_B16P/DQ2B) ; also on sheet 22
DA_B6: U11.AB8(IO_3B_AB8/DIFFIO_TX_B13P/DQ2B) ; also on sheet 22
DA_B7: U11.AA8(IO_3B_AA8/DIFFIO_TX_B13N/DQ2B) ; also on sheet 22
DA_B8: U11.W8(IO_3A_W8/DATA9/DIFFIO_TX_B4N/DQ1B) ; also on sheet 22
DA_B9: U11.U8(IO_3A_U8/DATA7/DIFFIO_TX_B2P/DQ1B) ; also on sheet 22
DA_G0: U11.T8(IO_3A_T8/CLKUSR/DIFFIO_RX_B5P/DQ1B) ; also on sheet 22
DA_G1: U11.P8(IO_3B_P8/DIFFIO_RX_B11N/DQSN2B) ; also on sheet 22
DA_G2: U11.N8(IO_3B_N8/DIFFIO_RX_B11P/DQS2B) ; also on sheet 22
DA_G3: U11.AB7(IO_3B_AB7/DIFFIO_TX_B12P) ; also on sheet 22
DA_G4: U11.AA7(IO_3B_AA7/DIFFIO_TX_B12N/DQ2B) ; also on sheet 22
DA_G5: U11.U7(IO_3A_U7/DATA5/DIFFIO_TX_B2N) ; also on sheet 22
DA_G6: U11.T7(IO_3A_T7/DATA14/DIFFIO_RX_B5N/DQ1B) ; also on sheet 22
DA_G7: U11.R7(IO_3A_R7/PR_READY/DIFFIO_TX_B8N/DQ1B) ; also on sheet 22
DA_G8: U11.P7(IO_3A_P7/DIFFIO_TX_B8P/DQ1B) ; also on sheet 22
DA_G9: U11.P6(IO_3A_P6/DATA10/DIFFIO_RX_B3N/DQSN1B) ; also on sheet 22
DA_R0: U11.U6(IO_3A_U6/DATA13/DIFFIO_TX_B6N/DQ1B) ; also on sheet 22
DA_R1: U11.V6(IO_3A_V6/DATA15/DIFFIO_TX_B6P/DQ1B) ; also on sheet 22
DA_R2: U11.AB6(IO_3B_AB6/DIFFIO_TX_B9N) ; also on sheet 22
DA_R3: U11.AB5(IO_3B_AB5/DIFFIO_TX_B9P/DQ2B) ; also on sheet 22
DA_R4: U11.Y3(IO_2A_Y3/DIFFIO_RX_L15P) ; also on sheet 22
DA_R5: U11.AA2(IO_2A_AA2/DIFFIO_TX_L16P/DQ1L) ; also on sheet 22
DA_R6: U11.AA1(IO_2A_AA1/DIFFIO_TX_L16N/DQ1L) ; also on sheet 22
DA_R7: U11.W2(IO_2A_W2/DIFFIO_RX_L15N) ; also on sheet 22
DA_R8: U11.U2(IO_2A_U2/DIFFIO_RX_L14P/DQ1L) ; also on sheet 22
DA_R9: U11.U1(IO_2A_U1/DIFFIO_RX_L14N/DQ1L) ; also on sheet 22
DADADDR0: J18.13E ; also on sheet 18
DADADDR1: J18.13F ; also on sheet 18
DADADDR2: J18.14A ; also on sheet 18
DADADDR3: J18.14B ; also on sheet 18
DADINTZ: J18.15E R170.2 ; also on sheet 18
DADMODE0: J18.15B ; also on sheet 18
DADMODE1: J18.15C ; also on sheet 18
DADOEZ: J18.12E R171.2 ; also on sheet 18
DADSEL0: J18.14D ; also on sheet 18
DADSEL1: J18.14E ; also on sheet 18
DADSTRB: J18.13C ; also on sheet 18
DB_B0: U11.U16(IO_4A_U16/DIFFIO_RX_B47N) ; also on sheet 22
DB_B1: U11.U15(IO_4A_U15/DIFFIO_RX_B35P/DQS5B) ; also on sheet 22
DB_B2: U11.W16(CLK3P_W16/DIFFIO_RX_B39P) ; also on sheet 22
DB_B3: U11.Y15(IO_4A_Y15/DIFFIO_RX_B30P/DQ4B) ; also on sheet 22
DB_B4: U11.AA15(IO_4A_AA15/DIFFIO_TX_B29P/DQ4B) ; also on sheet 22
DB_B5: U11.AB15(IO_4A_AB15/DIFFIO_TX_B29N/DQ4B) ; also on sheet 22
DB_B6: U11.P14(IO_4A_P14/DIFFIO_RX_B43N/DQSN6B) ; also on sheet 22
DB_B7: U11.R14(IO_4A_R14/DIFFIO_RX_B43P/DQS6B) ; also on sheet 22
DB_B8: U11.T14(IO_4A_T14/DIFFIO_RX_B35N/DQSN5B) ; also on sheet 22
DB_B9: U11.V14(CLK2N_V14/DIFFIO_RX_B31N) ; also on sheet 22
DB_G0: U11.Y14(IO_4A_Y14/DIFFIO_RX_B30N/DQ4B) ; also on sheet 22
DB_G1: U11.AA14(IO_4A_AA14/DIFFIO_TX_B28N/DQ4B) ; also on sheet 22
DB_G2: U11.T13(IO_4A_T13/DIFFIO_RX_B27P/DQS4B) ; also on sheet 22
DB_G3: U11.U13(IO_4A_U13/DIFFIO_RX_B26P/DQ4B) ; also on sheet 22
DB_G4: U11.V13(IO_4A_V13/DIFFIO_RX_B26N/DQ4B) ; also on sheet 22
DB_G5: U11.AA13(IO_4A_AA13/DIFFIO_TX_B28P) ; also on sheet 22
DB_G6: U11.AB13(RZQ_0_AB13/DIFFIO_TX_B25N) ; also on sheet 22
DB_G7: U11.P12(IO_3B_P12/DIFFIO_TX_B20P) ; also on sheet 22
DB_G8: U11.R12(IO_3B_R12/DIFFIO_TX_B20N/DQ3B) ; also on sheet 22
DB_G9: U11.T12(IO_4A_T12/DIFFIO_RX_B27N/DQSN4B) ; also on sheet 22
DB_R0: U11.U12(IO_3B_U12/DIFFIO_RX_B19P/DQS3B) ; also on sheet 22
DB_R1: U11.AA12(IO_3B_AA12/DIFFIO_TX_B24P/DQ3B) ; also on sheet 22
DB_R2: U11.AB12(IO_4A_AB12/DIFFIO_TX_B25P/DQ4B) ; also on sheet 22
DB_R3: U11.R11(IO_3B_R11/DIFFIO_RX_B22P/DQ3B) ; also on sheet 22
DB_R4: U11.U11(IO_3B_U11/DIFFIO_RX_B19N/DQSN3B) ; also on sheet 22
DB_R5: U11.Y11(IO_3B_Y11/DIFFIO_TX_B24N/DQ3B) ; also on sheet 22
DB_R6: U11.AB11(IO_3B_AB11/FPLL_BL_CLKOUT0,FPLL_BL_CLKOUTP,FPLL_BL_FB/DIFFIO_TX_B21P/DQ3B) ; also on sheet 22
DB_R7: U11.R10(IO_3B_R10/DIFFIO_RX_B22N/DQ3B) ; also on sheet 22
DB_R8: U11.T10(IO_3B_T10/DIFFIO_RX_B18N/DQ3B) ; also on sheet 22
DB_R9: U11.U10(IO_3B_U10/DIFFIO_RX_B14P/DQ2B) ; also on sheet 22
DCLK_PIN: R37.1 U11.V3(DCLK)
DMD_P3P3VA: C299.1 FB25.2 J18.1B J18.1C
DMD_P3P3VB: C304.1 FB27.1 J18.25E J18.25F
DMD_P3P3VC: C303.1 FB26.2 J19.1B J19.1C
DMD_P3P3VD: C307.1 FB28.1 J19.25E J19.25F
DMDSPARE0: J18.12D R168.1
DMDSPARE1: J18.11B R169.2 R172.1
F_OSC20M: U11.M9(IO_3B_M9/CLK0P,FPLL_BL_FBP/DIFFIO_RX_B15P) ; also on sheet 13
F_TCK: J5.1 R55.1 U11.V5(TCK)
F_TDI: J5.9 R51.2 U11.W5(TDI)
F_TDO: J5.3 U11.M5(TDO)
F_TEST0: S_TP1.1 U11.J7(IO_8A_J7/DIFFIO_RX_T27P/DQ4T)
F_TEST1: S_TP2.1 U11.J8(IO_8A_J8/DIFFIO_RX_T27N/DQ4T)
F_TEST2: S_TP3.1 U11.J9(IO_8A_J9/DIFFIO_RX_T29P/DQS4T)
F_TEST3: S_TP4.1 U11.K9(IO_7A_K9/DIFFIO_TX_T22N/DQ3T)
F_TMS: J5.5 R50.2 U11.P5(TMS)
F_VCCIO: C341.1 J5.4 L4.2 R38.1 R39.1 R40.1 R42.1 R43.1 R44.1 R50.1 R51.1 R197.1 R198.1 TP67.1 U11.A6(VCCIO8A) U11.A16(VCCIO7A) U11.AA16(VCCIO4A) U11.AA21(VCCIO4A) U11.AB16(VREFB4AN0) U11.B8(VREFB8AN0) U11.B19(VCCIO7A) U11.C7(VCCIO8A) U11.C12(VCCIO7A) U11.C14(VREFB7AN0) U11.C22(VCCIO7A) U11.D4(VCCIO2A) U11.D15(VCCIO7A) U11.E8(VCCIO8A) U11.E18(VCCIO7A) U11.F11(VCCIO7A) U11.F21(VCCIO7A) U11.G7(VCCIO8A) U11.G14(VCCIO7A) U11.H17(VCCIO7A) U11.J1(VCCIO2A) U11.K18(VCCIO5B) U11.L20(VREFB5BN0) U11.M17(VCCPD5B) U11.M19(VCCIO5B) U11.N18(VCCPD5B) U11.P20(VCCIO5A) U11.P21(VCCPD5A) U11.R1(VCCIO2A) U11.R8(VCCIO3B) U11.R18(VCCIO5A) U11.R20(VREFB5AN0) U11.T6(VCCIO3A) U11.T11(VCCIO3B) U11.U14(VCCIO4A) U11.U19(VCCIO4A) U11.W1(VREFB2AN0) U11.W6(VCCPD3A) U11.W10(VCCIO3B) U11.W15(VCCIO4A) U11.W20(VCCIO4A) U11.Y4(VCCIO2A) U11.Y7(VREFB3AN0) U11.Y8(VCCIO3A) U11.Y12(VREFB3BN0) U11.Y13(VCCIO3B) U30.6(VOS) ; also on sheet 25
ITE_DE: U11.Y10(IO_3B_Y10/DIFFIO_TX_B17N) ; also on sheet 22
ITE_FIELD: U11.V10(IO_3B_V10/DIFFIO_RX_B10P/DQ2B) ; also on sheet 22
ITE_HS: U11.AA10(IO_3B_AA10/DIFFIO_TX_B16N/DQ2B) ; also on sheet 22
ITE_VS: U11.AB10(IO_3B_AB10/FPLL_BL_CLKOUT1,FPLL_BL_CLKOUTN/DIFFIO_TX_B21N/DQ3B) ; also on sheet 22
LED12VON: D11.2(ANODE) R173.2
M_3DLR_GPIO78: U11.J17(IO_7A_J17/DIFFIO_TX_T10P/DQ2T) ; also on sheet 18
M_DCLKA_N: J18.5C ; also on sheet 18
M_DCLKA_P: J18.5B ; also on sheet 18
M_DCLKB_N: J18.21C ; also on sheet 18
M_DCLKB_P: J18.21B ; also on sheet 18
M_DDA00_N: J18.10E ; also on sheet 18
M_DDA00_P: J18.10D ; also on sheet 18
M_DDA01_N: J18.9C ; also on sheet 18
M_DDA01_P: J18.9B ; also on sheet 18
M_DDA02_N: J18.9F ; also on sheet 18
M_DDA02_P: J18.9E ; also on sheet 18
M_DDA03_N: J18.8B ; also on sheet 18
M_DDA03_P: J18.8A ; also on sheet 18
M_DDA04_N: J18.8E ; also on sheet 18
M_DDA04_P: J18.8D ; also on sheet 18
M_DDA05_N: J18.7C ; also on sheet 18
M_DDA05_P: J18.7B ; also on sheet 18
M_DDA06_N: J18.7F ; also on sheet 18
M_DDA06_P: J18.7E ; also on sheet 18
M_DDA07_N: J18.6B ; also on sheet 18
M_DDA07_P: J18.6A ; also on sheet 18
M_DDA08_N: J18.5F ; also on sheet 18
M_DDA08_P: J18.5E ; also on sheet 18
M_DDA09_N: J18.4B ; also on sheet 18
M_DDA09_P: J18.4A ; also on sheet 18
M_DDA10_N: J18.4E ; also on sheet 18
M_DDA10_P: J18.4D ; also on sheet 18
M_DDA11_N: J18.3C ; also on sheet 18
M_DDA11_P: J18.3B ; also on sheet 18
M_DDA12_N: J18.3F ; also on sheet 18
M_DDA12_P: J18.3E ; also on sheet 18
M_DDA13_N: J18.2B ; also on sheet 18
M_DDA13_P: J18.2A ; also on sheet 18
M_DDA14_N: J18.2E ; also on sheet 18
M_DDA14_P: J18.2D ; also on sheet 18
M_DDA15_N: J18.1F ; also on sheet 18
M_DDA15_P: J18.1E ; also on sheet 18
M_DDB00_N: J18.16E ; also on sheet 18
M_DDB00_P: J18.16D ; also on sheet 18
M_DDB01_N: J18.17C ; also on sheet 18
M_DDB01_P: J18.17B ; also on sheet 18
M_DDB02_N: J18.17F ; also on sheet 18
M_DDB02_P: J18.17E ; also on sheet 18
M_DDB03_N: J18.18B ; also on sheet 18
M_DDB03_P: J18.18A ; also on sheet 18
M_DDB04_N: J18.18E ; also on sheet 18
M_DDB04_P: J18.18D ; also on sheet 18
M_DDB05_N: J18.19C ; also on sheet 18
M_DDB05_P: J18.19B ; also on sheet 18
M_DDB06_N: J18.19F ; also on sheet 18
M_DDB06_P: J18.19E ; also on sheet 18
M_DDB07_N: J18.20B ; also on sheet 18
M_DDB07_P: J18.20A ; also on sheet 18
M_DDB08_N: J18.21F ; also on sheet 18
M_DDB08_P: J18.21E ; also on sheet 18
M_DDB09_N: J18.22B ; also on sheet 18
M_DDB09_P: J18.22A ; also on sheet 18
M_DDB10_N: J18.22E ; also on sheet 18
M_DDB10_P: J18.22D ; also on sheet 18
M_DDB11_N: J18.23C ; also on sheet 18
M_DDB11_P: J18.23B ; also on sheet 18
M_DDB12_N: J18.23F ; also on sheet 18
M_DDB12_P: J18.23E ; also on sheet 18
M_DDB13_N: J18.24B ; also on sheet 18
M_DDB13_P: J18.24A ; also on sheet 18
M_DDB14_N: J18.24E ; also on sheet 18
M_DDB14_P: J18.24D ; also on sheet 18
M_DDB15_N: J18.25C ; also on sheet 18
M_DDB15_P: J18.25B ; also on sheet 18
M_EXT_RSTZ: J18.11F ; also on sheet 17
M_GPIO67: U11.E2(IO_2A_E2/DIFFIO_RX_L11N/DQSN1L) ; also on sheet 14
M_GPIO68: U11.G2(IO_2A_G2/DIFFIO_RX_L10P/DQ1L) ; also on sheet 14
M_GPIO69: U11.L1(IO_2A_L1/DIFFIO_TX_L12N/DQ1L) ; also on sheet 14
M_GPIO70: U11.L2(IO_2A_L2/DIFFIO_TX_L12P) ; also on sheet 14
M_P1A0: U11.A5(IO_8A_A5/DIFFIO_TX_T32P/DQ4T) ; also on sheet 18
M_P1A1: U11.B5(IO_8A_B5/DIFFIO_TX_T32N) ; also on sheet 18
M_P1A2: U11.B6(IO_8A_B6/DIFFIO_TX_T34P/DQ5T) ; also on sheet 18
M_P1A3: U11.C6(IO_8A_C6/DIFFIO_TX_T36P/DQ5T) ; also on sheet 18
M_P1A4: U11.D6(IO_8A_D6/DIFFIO_TX_T36N/DQ5T) ; also on sheet 18
M_P1A5: U11.G6(IO_8A_G6/DIFFIO_RX_T39P/DQ5T) ; also on sheet 18
M_P1A6: U11.H6(IO_8A_H6/DIFFIO_RX_T39N/DQ5T) ; also on sheet 18
M_P1A7: U11.A7(IO_8A_A7/DIFFIO_RX_T35N/DQ5T) ; also on sheet 18
M_P1A8: U11.B7(IO_8A_B7/DIFFIO_TX_T34N/DQ5T) ; also on sheet 18
M_P1A9: U11.D7(IO_8A_D7/DIFFIO_TX_T38P) ; also on sheet 18
M_P1B0: U11.E7(IO_8A_E7/DIFFIO_TX_T40N) ; also on sheet 18
M_P1B1: U11.F7(IO_8A_F7/DIFFIO_TX_T40P/DQ5T) ; also on sheet 18
M_P1B2: U11.A8(IO_8A_A8/DIFFIO_RX_T35P/DQ5T) ; also on sheet 18
M_P1B3: U11.C8(IO_8A_C8/DIFFIO_TX_T38N/DQ5T) ; also on sheet 18
M_P1B4: U11.G8(IO_8A_G8/FPLL_TL_CLKOUT1,FPLL_TL_CLKOUTN/DIFFIO_TX_T28N/DQ4T) ; also on sheet 18
M_P1B5: U11.H8(IO_8A_H8/FPLL_TL_CLKOUT0,FPLL_TL_CLKOUTP,FPLL_TL_FB/DIFFIO_TX_T28P/DQ4T) ; also on sheet 18
M_P1B6: U11.A9(IO_8A_A9/DIFFIO_TX_T30N/DQ4T) ; also on sheet 18
M_P1B7: U11.C9(IO_8A_C9/DIFFIO_RX_T31N/DQ4T) ; also on sheet 18
M_P1B8: U11.D9(IO_8A_D9/DIFFIO_RX_T37N/DQSN5T) ; also on sheet 18
M_P1B9: U11.E9(IO_8A_E9/DIFFIO_RX_T37P/DQS5T) ; also on sheet 18
M_P1C0: U11.F9(IO_8A_F9/CLK8N,FPLL_TL_FBN/DIFFIO_RX_T33N) ; also on sheet 18
M_P1C1: U11.H9(IO_8A_H9/DIFFIO_RX_T29N/DQSN4T) ; also on sheet 18
M_P1C2: U11.A10(IO_8A_A10/DIFFIO_TX_T30P) ; also on sheet 18
M_P1C3: U11.B10(IO_8A_B10/DIFFIO_RX_T31P/DQ4T) ; also on sheet 18
M_P1C4: U11.E10(IO_8A_E10/CLK8P,FPLL_TL_FBP/DIFFIO_RX_T33P) ; also on sheet 18
M_P1C5: U11.F10(CLK9N_F10/DIFFIO_RX_T25N) ; also on sheet 18
M_P1C6: U11.H10(IO_7A_H10/DIFFIO_TX_T16N) ; also on sheet 18
M_P1C7: U11.J11(IO_7A_J11/DIFFIO_TX_T16P/DQ2T) ; also on sheet 18
M_P1C8: U11.B11(RZQ_2_B11/DIFFIO_TX_T24N) ; also on sheet 18
M_P1C9: U11.C11(IO_7A_C11/DIFFIO_TX_T24P/DQ3T) ; also on sheet 18
M_P1DATEN: U11.G11(IO_7A_G11/DIFFIO_TX_T18P/DQ3T) ; also on sheet 18
M_P1HS: U11.H11(IO_7A_H11/DIFFIO_RX_T21P/DQS3T) ; also on sheet 18
M_P1VS: U11.A12(IO_7A_A12/DIFFIO_TX_T20N/DQ3T) ; also on sheet 18
M_P2A0: U11.B12(IO_7A_B12/DIFFIO_TX_T20P/DQ3T) ; also on sheet 18
M_P2A1: U11.D12(IO_7A_D12/DIFFIO_RX_T23P/DQ3T) ; also on sheet 18
M_P2A2: U11.E12(IO_7A_E12/DIFFIO_RX_T23N/DQ3T) ; also on sheet 18
M_P2A3: U11.F12(IO_7A_F12/DIFFIO_TX_T18N/DQ3T) ; also on sheet 18
M_P2A4: U11.G12(IO_7A_G12/DIFFIO_RX_T21N/DQSN3T) ; also on sheet 18
M_P2A5: U11.A13(IO_7A_A13/DIFFIO_TX_T14N/DQ2T) ; also on sheet 18
M_P2A6: U11.B13(IO_7A_B13/DIFFIO_TX_T14P) ; also on sheet 18
M_P2A7: U11.C13(IO_7A_C13/DIFFIO_RX_T19N/DQ3T) ; also on sheet 18
M_P2A8: U11.D13(IO_7A_D13/DIFFIO_RX_T19P/DQ3T) ; also on sheet 18
M_P2A9: U11.F13(IO_7A_F13/DIFFIO_RX_T15N/DQ2T) ; also on sheet 18
M_P2B0: U11.G13(CLK10N_G13/DIFFIO_RX_T17N) ; also on sheet 18
M_P2B1: U11.H13(CLK10P_H13/DIFFIO_RX_T17P) ; also on sheet 18
M_P2B2: U11.J13(IO_7A_J13/DIFFIO_RX_T13N/DQSN2T) ; also on sheet 18
M_P2B3: U11.A14(IO_7A_A14/DIFFIO_TX_T8N) ; also on sheet 18
M_P2B4: U11.E14(IO_7A_E14/DIFFIO_RX_T15P/DQ2T) ; also on sheet 18
M_P2B5: U11.F14(IO_7A_F14/DIFFIO_TX_T12N/DQ2T) ; also on sheet 18
M_P2B6: U11.H14(IO_7A_H14/DIFFIO_RX_T13P/DQS2T) ; also on sheet 18
M_P2B7: U11.A15(IO_7A_A15/DIFFIO_TX_T8P/DQ1T) ; also on sheet 18
M_P2B8: U11.B15(IO_7A_B15/DIFFIO_RX_T11N/DQ2T) ; also on sheet 18
M_P2B9: U11.C15(IO_7A_C15/DIFFIO_RX_T11P/DQ2T) ; also on sheet 18
M_P2C0: U11.E15(IO_7A_E15/DIFFIO_RX_T7P/DQ1T) ; also on sheet 18
M_P2C1: U11.F15(IO_7A_F15/DIFFIO_RX_T7N/DQ1T) ; also on sheet 18
M_P2C2: U11.G15(IO_7A_G15/DIFFIO_TX_T12P/DQ2T) ; also on sheet 18
M_P2C3: U11.B16(IO_7A_B16/DIFFIO_TX_T2P/DQ1T) ; also on sheet 18
M_P2C4: U11.C16(IO_7A_C16/DIFFIO_TX_T2N/DQ1T) ; also on sheet 18
M_P2C5: U11.E16(IO_7A_E16/DIFFIO_RX_T3N/DQ1T) ; also on sheet 18
M_P2C6: U11.G16(IO_7A_G16/DIFFIO_TX_T4N/DQ1T) ; also on sheet 18
M_P2C7: U11.H16(CLK11P_H16/DIFFIO_RX_T9P) ; also on sheet 18
M_P2C8: U11.G17(IO_7A_G17/DIFFIO_TX_T4P/DQ1T) ; also on sheet 18
M_P2C9: U11.G18(IO_7A_G18/DIFFIO_RX_T5P/DQS1T) ; also on sheet 18
M_PCLK1: U11.D17(IO_7A_D17/DIFFIO_RX_T3P/DQ1T) ; also on sheet 18
M_SCTLA_N: J18.6E ; also on sheet 18
M_SCTLA_P: J18.6D ; also on sheet 18
M_SCTLB_N: J18.20E ; also on sheet 18
M_SCTLB_P: J18.20D ; also on sheet 18
MSEL0: R42.2 R46.1 U11.L6(MSEL0)
MSEL1: R43.2 R47.1 U11.J6(MSEL1)
MSEL2: R48.1 U11.A2(MSEL2)
MSEL3: R49.1 U11.E5(MSEL3)
MSEL4: R44.2 U11.F3(MSEL4)
nCONFIG: R39.2 TP11.1 U11.A4(NCONFIG)
nSTATUS: R40.2 TP12.1 U11.H5(NSTATUS)
P1P1V: C320.1 C321.1 L1.2 R179.1 TP63.1 ; also on sheet 25 26 27
P1P8V: C323.1 L2.2 R180.1 TP64.1 ; also on sheet 12 24 26 27
P1P8V_A: C339.1 TP66.1 U29.7(OUT7) U29.8(OUT8) ; also on sheet 26 27
P1P8V_ITEA: C348.1 TP69.1 U32.3(VOUT) ; also on sheet 24
P2P5V_FAUXPLL: C344.1 TP68.1 U31.5(OUT) ; also on sheet 25
P3P3V: C64.1 C220.1 C221.1 C222.1 C223.1 C224.1 C225.1 C298.1 C300.1 C301.1 C302.1 C305.1 C306.1 C308.1 C309.1 C334.1 C340.1 C343.1 C346.1 C347.1 FB25.1 FB26.1 FB27.2 FB28.2 L3.2 R41.1 R52.1 R53.1 R54.1 R150.1 R151.1 R152.1 R153.1 R154.1 R156.1 R157.1 R169.1 R170.1 R171.1 R174.1 R175.1 R189.1 R191.1 R196.1 TP65.1 U12.8(VCC) U23.29(VIO) U23.43(VCC) U24.29(VIO) U24.43(VCC) U25.29(VIO) U25.43(VCC) U29.5(IN5) U29.6(IN6) U31.1(IN) U32.1(VIN) ; also on sheet 9 10 11 12 13 14 15 16 17 18 22 24 26 27 28
PCLK: U11.N9(CLK1P_N9/DIFFIO_RX_B23P) ; also on sheet 22
S_3DLR_GPIO78: U11.T19(RZQ_1_T19/DIFFIO_TX_R1P/DQ1R) ; also on sheet 11
S_DCLKA_N: J19.5C ; also on sheet 11
S_DCLKA_P: J19.5B ; also on sheet 11
S_DCLKB_N: J19.21C ; also on sheet 11
S_DCLKB_P: J19.21B ; also on sheet 11
S_DDA00_N: J19.10E ; also on sheet 11
S_DDA00_P: J19.10D ; also on sheet 11
S_DDA01_N: J19.9C ; also on sheet 11
S_DDA01_P: J19.9B ; also on sheet 11
S_DDA02_N: J19.9F ; also on sheet 11
S_DDA02_P: J19.9E ; also on sheet 11
S_DDA03_N: J19.8B ; also on sheet 11
S_DDA03_P: J19.8A ; also on sheet 11
S_DDA04_N: J19.8E ; also on sheet 11
S_DDA04_P: J19.8D ; also on sheet 11
S_DDA05_N: J19.7C ; also on sheet 11
S_DDA05_P: J19.7B ; also on sheet 11
S_DDA06_N: J19.7F ; also on sheet 11
S_DDA06_P: J19.7E ; also on sheet 11
S_DDA07_N: J19.6B ; also on sheet 11
S_DDA07_P: J19.6A ; also on sheet 11
S_DDA08_N: J19.5F ; also on sheet 11
S_DDA08_P: J19.5E ; also on sheet 11
S_DDA09_N: J19.4B ; also on sheet 11
S_DDA09_P: J19.4A ; also on sheet 11
S_DDA10_N: J19.4E ; also on sheet 11
S_DDA10_P: J19.4D ; also on sheet 11
S_DDA11_N: J19.3C ; also on sheet 11
S_DDA11_P: J19.3B ; also on sheet 11
S_DDA12_N: J19.3F ; also on sheet 11
S_DDA12_P: J19.3E ; also on sheet 11
S_DDA13_N: J19.2B ; also on sheet 11
S_DDA13_P: J19.2A ; also on sheet 11
S_DDA14_N: J19.2E ; also on sheet 11
S_DDA14_P: J19.2D ; also on sheet 11
S_DDA15_N: J19.1F ; also on sheet 11
S_DDA15_P: J19.1E ; also on sheet 11
S_DDB00_N: J19.16E ; also on sheet 11
S_DDB00_P: J19.16D ; also on sheet 11
S_DDB01_N: J19.17C ; also on sheet 11
S_DDB01_P: J19.17B ; also on sheet 11
S_DDB02_N: J19.17F ; also on sheet 11
S_DDB02_P: J19.17E ; also on sheet 11
S_DDB03_N: J19.18B ; also on sheet 11
S_DDB03_P: J19.18A ; also on sheet 11
S_DDB04_N: J19.18E ; also on sheet 11
S_DDB04_P: J19.18D ; also on sheet 11
S_DDB05_N: J19.19C ; also on sheet 11
S_DDB05_P: J19.19B ; also on sheet 11
S_DDB06_N: J19.19F ; also on sheet 11
S_DDB06_P: J19.19E ; also on sheet 11
S_DDB07_N: J19.20B ; also on sheet 11
S_DDB07_P: J19.20A ; also on sheet 11
S_DDB08_N: J19.21F ; also on sheet 11
S_DDB08_P: J19.21E ; also on sheet 11
S_DDB09_N: J19.22B ; also on sheet 11
S_DDB09_P: J19.22A ; also on sheet 11
S_DDB10_N: J19.22E ; also on sheet 11
S_DDB10_P: J19.22D ; also on sheet 11
S_DDB11_N: J19.23C ; also on sheet 11
S_DDB11_P: J19.23B ; also on sheet 11
S_DDB12_N: J19.23F ; also on sheet 11
S_DDB12_P: J19.23E ; also on sheet 11
S_DDB13_N: J19.24B ; also on sheet 11
S_DDB13_P: J19.24A ; also on sheet 11
S_DDB14_N: J19.24E ; also on sheet 11
S_DDB14_P: J19.24D ; also on sheet 11
S_DDB15_N: J19.25C ; also on sheet 11
S_DDB15_P: J19.25B ; also on sheet 11
S_FLASH0_WP#: R150.2 U23.16(WP#/ACC)
S_FLASH1_WP#: R151.2 U24.16(WP#/ACC)
S_FLASH2_WP#: R157.2 U25.16(WP#/ACC)
S_P1A0: U11.H18(IO_7A_H18/DIFFIO_RX_T5N/DQSN1T) ; also on sheet 11
S_P1A1: U11.J18(IO_7A_J18/DIFFIO_TX_T6N/DQ1T) ; also on sheet 11
S_P1A2: U11.J19(IO_7A_J19/DIFFIO_TX_T6P) ; also on sheet 11
S_P1A3: U11.K16(IO_7A_K16/DIFFIO_TX_T10N/DQ2T) ; also on sheet 11
S_P1A4: U11.K17(IO_5B_K17/DIFFIO_RX_R13P/DQS2R) ; also on sheet 11
S_P1A5: U11.K19(IO_7A_K19/DIFFIO_RX_T1N) ; also on sheet 11
S_P1A6: U11.K20(IO_7A_K20/DIFFIO_RX_T1P) ; also on sheet 11
S_P1A7: U11.K21(IO_5B_K21/DIFFIO_TX_R16P/DQ2R) ; also on sheet 11
S_P1A8: U11.K22(IO_5B_K22/DIFFIO_TX_R16N) ; also on sheet 11
S_P1A9: U11.L17(IO_5B_L17/DIFFIO_RX_R13N/DQSN2R) ; also on sheet 11
S_P1B0: U11.L18(IO_5B_L18/DIFFIO_RX_R15N/DQ2R) ; also on sheet 11
S_P1B1: U11.L19(IO_5B_L19/DIFFIO_RX_R15P/DQ2R) ; also on sheet 11
S_P1B2: U11.L22(IO_5B_L22/FPLL_BR_CLKOUT1,FPLL_BR_CLKOUTN/DIFFIO_TX_R12N/DQ2R) ; also on sheet 11
S_P1B3: U11.M16(CLK6N_M16/DIFFIO_RX_R9N) ; also on sheet 11
S_P1B4: U11.M18(IO_5B_M18/DIFFIO_RX_R11N/DQ2R) ; also on sheet 11
S_P1B5: U11.M20(IO_5B_M20/DIFFIO_TX_R14P) ; also on sheet 11
S_P1B6: U11.M21(IO_5B_M21/DIFFIO_TX_R14N/DQ2R) ; also on sheet 11
S_P1B7: U11.M22(IO_5B_M22/FPLL_BR_CLKOUT0,FPLL_BR_CLKOUTP,FPLL_BR_FB/DIFFIO_TX_R12P/DQ2R) ; also on sheet 11
S_P1B8: U11.N19(IO_5B_N19/DIFFIO_RX_R11P/DQ2R) ; also on sheet 11
S_P1B9: U11.N20(IO_5B_N20/DIFFIO_TX_R10P/DQ2R) ; also on sheet 11
S_P1C0: U11.N21(IO_5B_N21/DIFFIO_TX_R10N/DQ2R) ; also on sheet 11
S_P1C1: U11.P16(IO_5A_P16/DIFFIO_RX_R8P/DQ1R) ; also on sheet 11
S_P1C2: U11.P17(IO_5A_P17/DIFFIO_RX_R8N/DQ1R) ; also on sheet 11
S_P1C3: U11.P18(IO_5A_P18/DIFFIO_TX_R7N) ; also on sheet 11
S_P1C4: U11.P19(IO_5A_P19/DIFFIO_TX_R7P/DQ1R) ; also on sheet 11
S_P1C5: U11.P22(IO_5A_P22/DEV_CLRN/DIFFIO_TX_R5N/DQ1R) ; also on sheet 11
S_P1C6: U11.R15(IO_5A_R15/DIFFIO_RX_R4N/DQ1R) ; also on sheet 11
S_P1C7: U11.R16(IO_5A_R16/DIFFIO_RX_R6P/DQS1R) ; also on sheet 11
S_P1C8: U11.R17(IO_5A_R17/DIFFIO_RX_R6N/DQSN1R) ; also on sheet 11
S_P1C9: U11.R21(IO_5A_R21/DEV_OE/DIFFIO_TX_R5P) ; also on sheet 11
S_P1DATEN: U11.R22(IO_5A_R22/CVP_CONFDONE/DIFFIO_TX_R3N/DQ1R) ; also on sheet 11
S_P1HS: U11.T15(IO_5A_T15/DIFFIO_RX_R4P/DQ1R) ; also on sheet 11
S_P1VS: U11.T17(IO_5A_T17/CRC_ERROR/DIFFIO_RX_R2N) ; also on sheet 11
S_P2A0: U11.T20(IO_5A_T20/PR_REQUEST/DIFFIO_TX_R1N/DQ1R) ; also on sheet 11
S_P2A1: U11.T22(IO_5A_T22/NCEO/DIFFIO_TX_R3P/DQ1R) ; also on sheet 11
S_P2A2: U11.U22(IO_4A_U22/DIFFIO_TX_B45N/DQ6B) ; also on sheet 11
S_P2A3: U11.W22(IO_4A_W22/DIFFIO_TX_B41P/DQ6B) ; also on sheet 11
S_P2A4: U11.Y22(IO_4A_Y22/DIFFIO_TX_B41N) ; also on sheet 11
S_P2A5: U11.AA22(IO_4A_AA22/DIFFIO_TX_B40P/DQ5B) ; also on sheet 11
S_P2A6: U11.AB22(IO_4A_AB22/DIFFIO_TX_B40N/DQ5B) ; also on sheet 11
S_P2A7: U11.U21(IO_4A_U21/DIFFIO_TX_B48N/DQ6B) ; also on sheet 11
S_P2A8: U11.V21(IO_4A_V21/DIFFIO_TX_B45P/DQ6B) ; also on sheet 11
S_P2A9: U11.W21(IO_4A_W21/DIFFIO_TX_B44P) ; also on sheet 11
S_P2B0: U11.Y21(IO_4A_Y21/DIFFIO_TX_B44N/DQ6B) ; also on sheet 11
S_P2B1: U11.AB21(IO_4A_AB21/DIFFIO_TX_B33P/DQ5B) ; also on sheet 11
S_P2B2: U11.U20(IO_4A_U20/DIFFIO_TX_B48P/DQ6B) ; also on sheet 11
S_P2B3: U11.V20(IO_4A_V20/DIFFIO_RX_B38N/DQ5B) ; also on sheet 11
S_P2B4: U11.Y20(IO_4A_Y20/DIFFIO_RX_B42N/DQ6B) ; also on sheet 11
S_P2B5: U11.AA20(IO_4A_AA20/DIFFIO_TX_B37P/DQ5B) ; also on sheet 11
S_P2B6: U11.AB20(IO_4A_AB20/DIFFIO_TX_B33N) ; also on sheet 11
S_P2B7: U11.V19(IO_4A_V19/DIFFIO_RX_B46N/DQ6B) ; also on sheet 11
S_P2B8: U11.W19(IO_4A_W19/DIFFIO_RX_B38P/DQ5B) ; also on sheet 11
S_P2B9: U11.Y19(IO_4A_Y19/DIFFIO_RX_B42P/DQ6B) ; also on sheet 11
S_P2C0: U11.AA19(IO_4A_AA19/DIFFIO_TX_B37N/DQ5B) ; also on sheet 11
S_P2C1: U11.V18(IO_4A_V18/DIFFIO_RX_B46P/DQ6B) ; also on sheet 11
S_P2C2: U11.AA18(IO_4A_AA18/DIFFIO_TX_B36P) ; also on sheet 11
S_P2C3: U11.AB18(IO_4A_AB18/DIFFIO_TX_B32P/DQ4B) ; also on sheet 11
S_P2C4: U11.U17(IO_4A_U17/DIFFIO_RX_B47P) ; also on sheet 11
S_P2C5: U11.Y17(IO_4A_Y17/DIFFIO_RX_B34P/DQ5B) ; also on sheet 11
S_P2C6: U11.AA17(IO_4A_AA17/DIFFIO_TX_B36N/DQ5B) ; also on sheet 11
S_P2C7: U11.AB17(IO_4A_AB17/DIFFIO_TX_B32N/DQ4B) ; also on sheet 11
S_P2C8: U11.V16(CLK3N_V16/DIFFIO_RX_B39N) ; also on sheet 11
S_P2C9: U11.Y16(IO_4A_Y16/DIFFIO_RX_B34N/DQ5B) ; also on sheet 11
S_PCLK1: U11.T18(IO_5A_T18/INIT_DONE/DIFFIO_RX_R2P) ; also on sheet 11
S_PM_CSZ0: R154.2 U22.D13(PM_CSZ_0) U23.32(CE#)
S_PM_CSZ1: R153.2 U22.E12(PM_CSZ_1) U24.32(CE#)
S_PM_CSZ2: R152.2 U22.A13(PM_CSZ_2) U25.32(CE#)
S_PM_OEZ: U22.C13(PM_OEZ) U23.34(OE#) U24.34(OE#) U25.34(OE#)
S_PM_WEZ: R155.1 U23.13(WE#) U24.13(WE#) U25.13(WE#)
S_PMADDR00: U22.C7(PM_ADDR_00) U23.31(A0) U24.31(A0) U25.31(A0)
S_PMADDR01: U22.A7(PM_ADDR_01) U23.26(A1) U24.26(A1) U25.26(A1)
S_PMADDR02: U22.B7(PM_ADDR_02) U23.25(A2) U24.25(A2) U25.25(A2)
S_PMADDR03: U22.C8(PM_ADDR_03) U23.24(A3) U24.24(A3) U25.24(A3)
S_PMADDR04: U22.D8(PM_ADDR_04) U23.23(A4) U24.23(A4) U25.23(A4)
S_PMADDR05: U22.A8(PM_ADDR_05) U23.22(A5) U24.22(A5) U25.22(A5)
S_PMADDR06: U22.B8(PM_ADDR_06) U23.21(A6) U24.21(A6) U25.21(A6)
S_PMADDR07: U22.C9(PM_ADDR_07) U23.20(A7) U24.20(A7) U25.20(A7)
S_PMADDR08: U22.D9(PM_ADDR_08) U23.10(A8) U24.10(A8) U25.10(A8)
S_PMADDR09: U22.E9(PM_ADDR_09) U23.9(A9) U24.9(A9) U25.9(A9)
S_PMADDR10: U22.A9(PM_ADDR_10) U23.8(A10) U24.8(A10) U25.8(A10)
S_PMADDR11: U22.B9(PM_ADDR_11) U23.7(A11) U24.7(A11) U25.7(A11)
S_PMADDR12: U22.C10(PM_ADDR_12) U23.6(A12) U24.6(A12) U25.6(A12)
S_PMADDR13: U22.D10(PM_ADDR_13) U23.5(A13) U24.5(A13) U25.5(A13)
S_PMADDR14: U22.E10(PM_ADDR_14) U23.4(A14) U24.4(A14) U25.4(A14)
S_PMADDR15: U22.C11(PM_ADDR_15) U23.3(A15) U24.3(A15) U25.3(A15)
S_PMADDR16: U22.D11(PM_ADDR_16) U23.54(A16) U24.54(A16) U25.54(A16)
S_PMADDR17: U22.A11(PM_ADDR_17) U23.19(A17) U24.19(A17) U25.19(A17)
S_PMADDR18: U22.B11(PM_ADDR_18) U23.18(A18) U24.18(A18) U25.18(A18)
S_PMADDR19: U22.C12(PM_ADDR_19) U23.11(A19) U24.11(A19) U25.11(A19)
S_PMADDR20: U22.D12(PM_ADDR_20) U23.12(A20) U24.12(A20) U25.12(A20)
S_PMADDR21_GPIO35: R149.1 U22.E11(PM_ADDR_21) U23.15(A21) U24.15(A21) U25.15(A21)
S_PMADDR22_GPIO36: R148.1 U22.A12(PM_ADDR_22) U23.2(A22) U24.2(A22) U25.2(A22)
S_PMDATA_00: U22.B13(PM_DATA_00) U23.35(DQ0) U24.35(DQ0) U25.35(DQ0)
S_PMDATA_01: U22.C14(PM_DATA_01) U23.37(DQ1) U24.37(DQ1) U25.37(DQ1)
S_PMDATA_02: U22.D14(PM_DATA_02) U23.39(DQ2) U24.39(DQ2) U25.39(DQ2)
S_PMDATA_03: U22.E13(PM_DATA_03) U23.41(DQ3) U24.41(DQ3) U25.41(DQ3)
S_PMDATA_04: U22.A14(PM_DATA_04) U23.44(DQ4) U24.44(DQ4) U25.44(DQ4)
S_PMDATA_05: U22.B14(PM_DATA_05) U23.46(DQ5) U24.46(DQ5) U25.46(DQ5)
S_PMDATA_06: U22.C15(PM_DATA_06) U23.48(DQ6) U24.48(DQ6) U25.48(DQ6)
S_PMDATA_07: U22.D15(PM_DATA_07) U23.50(DQ7) U24.50(DQ7) U25.50(DQ7)
S_PMDATA_08: U22.E14(PM_DATA_08) U23.36(DQ8) U24.36(DQ8) U25.36(DQ8)
S_PMDATA_09: U22.C16(PM_DATA_09) U23.38(DQ9) U24.38(DQ9) U25.38(DQ9)
S_PMDATA_10: U22.D16(PM_DATA_10) U23.40(DQ10) U24.40(DQ10) U25.40(DQ10)
S_PMDATA_11: U22.B15(PM_DATA_11) U23.42(DQ11) U24.42(DQ11) U25.42(DQ11)
S_PMDATA_12: U22.A15(PM_DATA_12) U23.45(DQ12) U24.45(DQ12) U25.45(DQ12)
S_PMDATA_13: U22.A16(PM_DATA_13) U23.47(DQ13) U24.47(DQ13) U25.47(DQ13)
S_PMDATA_14: U22.B16(PM_DATA_14) U23.49(DQ14) U24.49(DQ14) U25.49(DQ14)
S_PMDATA_15: U22.C17(PM_DATA_15) U23.51(DQ15) U24.51(DQ15) U25.51(DQ15)
S_PMWEZ_PIN: R155.2 U22.B12(PM_WEZ)
S_POSENSE: U23.14(RESET#) U24.14(RESET#) U25.14(RESET#) ; also on sheet 10 13
S_SCTLA_N: J19.6E ; also on sheet 11
S_SCTLA_P: J19.6D ; also on sheet 11
S_SCTLB_N: J19.20E ; also on sheet 11
S_SCTLB_P: J19.20D ; also on sheet 11
SFLASH_RYBYZ: R156.2 U23.17(RY/BY#) U24.17(RY/BY#) U25.17(RY/BY#)
SSP0_CLK: J18.10B U11.D3(IO_2A_D3/DIFFIO_RX_L11P/DQS1L) ; also on sheet 10 17
SSP0_CSZ0_DAD1: J18.12A ; also on sheet 17
SSP0_CSZ1_DMD: J18.11C ; also on sheet 17
SSP0_CSZ2_FPGA: U11.C2(IO_2A_C2/DIFFIO_TX_L9P/DQ1L) ; also on sheet 17
SSP0_CSZ5_DAD2: J18.12B ; also on sheet 14
SSP0_RXD_S2M: J18.11E U11.G1(IO_2A_G1/DIFFIO_RX_L10N/DQ1L) ; also on sheet 10 17
SSP0_TXD_M2S: J18.10A U11.C1(IO_2A_C1/DIFFIO_TX_L9N) ; also on sheet 10 17
N20556337: C327.1 R182.2
N20557124: C330.1 R184.2
N20590731: D5.2(ANODE) R41.2
N20590733: Q1.G R45.2
N20590858: D5.1(CATHODE) Q1.D
N20778960: C337.1 R193.2

Not connected (* = marked no-connect by the designer): J5 6* 7* 8*; J18 13A* 13B*; J19 10A* 10B* 11B* 11C* 11E* 11F* 12A* 12B* 12D* 12E* 13A* 13B* 13C* 13E* 13F* 14A* 14B* 14D* 14E* 15B* 15C* 15E*; U11 AA5(AS_DATA2_3A_AA5/DATA2)* H15(CLK11N_H15/DIFFIO_RX_T9N) K7(IO_8A_K7/DIFFIO_TX_T26N/DQ4T)* L7(IO_8A_L7/DIFFIO_TX_T26P/DQ4T)* L8(IO_7A_L8/DIFFIO_TX_T22P)* M6(IO_3A_M6/PR_DONE/DIFFIO_RX_B7N)* M7(IO_3A_M7/PR_ERROR/DIFFIO_RX_B7P)* M8(IO_3B_M8/CLK0N,FPLL_BL_FBN/DIFFIO_RX_B15N)* N1(IO_2A_N1/DIFFIO_TX_L13N/DQ1L)* N2(IO_2A_N2/DIFFIO_TX_L13P/DQ1L)* N6(IO_3A_N6/DATA12/DIFFIO_RX_B3P/DQS1B)* N16(CLK6P_N16/DIFFIO_RX_R9P)* P9(CLK1N_P9/DIFFIO_RX_B23N)* R5(IO_3A_R5/DATA8/DIFFIO_RX_B1P/DQ1B)* R6(IO_3A_R6/DATA6/DIFFIO_RX_B1N/DQ1B)* T4(AS_DATA3_3A_T4/DATA3)* V15(CLK2P_V15/DIFFIO_RX_B31P)*; U22 A6(PM_BLSZ_0)* B6(PM_BLSZ_1)*; U23 1(NC)* 27(NC)* 28(NC)* 30(NC)* 53(NC)* 55(NC)* 56(NC)*; U24 1(NC)* 27(NC)* 28(NC)* 30(NC)* 53(NC)* 55(NC)* 56(NC)*; U25 1(NC)* 27(NC)* 28(NC)* 30(NC)* 53(NC)* 55(NC)* 56(NC)*; U29 1(NC)*

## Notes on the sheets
sheet 1
- IMPORTANT NOTICE FOR TI REFERENCE DESIGNS
- Texas Instruments Incorporated ("TI") reference designs are solely intended to assist designers (“Buyers”) who are developing systems that incorporate TI semiconductor products (also referred to herein
  as “components”). Buyer understands and agrees that Buyer remains responsible for using its independent analysis, evaluation and judgment in designing Buyer’s systems and products.
  TI reference designs have been created using standard laboratory conditions and engineering practices. TI has not conducted any testing other than that specifically described in the published documentation
  for a particular reference design. TI may make corrections, enhancements, improvements and other changes to its reference designs.
  Buyers are authorized to use TI reference designs with the TI component(s) identified in each particular reference design and to modify the reference design in the development of their end products.
  HOWEVER, NO OTHER LICENSE, EXPRESS OR IMPLIED, BY ESTOPPEL OR OTHERWISE TO ANY OTHER TI INTELLECTUAL PROPERTY RIGHT, AND NO LICENSE TO ANY
  THIRD PARTY TECHNOLOGY OR INTELLECTUAL PROPERTY RIGHT, IS GRANTED HEREIN, including but not limited to any patent right, copyright, mask work right, or other intellectual property
  right relating to any combination, machine, or process in which TI components or services are used. Information published by TI regarding third-party products or services does not constitute a license to
  use such products or services, or a warranty or endorsement thereof. Use of such information may require a license from a third party under the patents or other intellectual property of the third
  party, or a license from TI under the patents or other intellectual property of TI.
  TI REFERENCE DESIGNS ARE PROVIDED "AS IS". TI MAKES NO WARRANTIES OR REPRESENTATIONS WITH REGARD TO THE REFERENCE DESIGNS OR USE OF
  THE REFERENCE DESIGNS, EXPRESS, IMPLIED OR STATUTORY, INCLUDING ACCURACY OR COMPLETENESS. TI DISCLAIMS ANY WARRANTY OF TITLE AND
  ANY IMPLIED WARRANTIES OF MERCHANTABILITY, FITNESS FOR A PARTICULAR PURPOSE, QUIET ENJOYMENT, QUIET POSSESSION, AND NON-INFRINGEMENT
  OF ANY THIRD PARTY INTELLECTUAL PROPERTY RIGHTS WITH REGARD TO TI REFERENCE DESIGNS OR USE THEREOF. TI SHALL NOT BE LIABLE FOR AND SHALL
  NOT DEFEND OR INDEMNIFY BUYERS AGAINST ANY THIRD PARTY INFRINGEMENT CLAIM THAT RELATES TO OR IS BASED ON A COMBINATION OF COMPONENTS
  PROVIDED IN A TI REFERENCE DESIGN. IN NO EVENT SHALL TI BE LIABLE FOR ANY ACTUAL, SPECIAL, INCIDENTAL, CONSEQUENTIAL OR INDIRECT DAMAGES,
  HOWEVER CAUSED, ON ANY THEORY OF LIABILITY AND WHETHER OR NOT TI HAS BEEN ADVISED OF THE POSSIBILITY OF SUCH DAMAGES, ARISING IN ANY WAY
  OUT OF TI REFERENCE DESIGNS OR BUYER’S USE OF TI REFERENCE DESIGNS.
  TI reserves the right to make corrections, enhancements, improvements and other changes to its semiconductor products and services per JESD46, latest issue, and to discontinue any product or
  service per JESD48, latest issue. Buyers should obtain the latest relevant information before placing orders and should verify that such information is current and complete. All semiconductor products
  are sold subject to TI’s terms and conditions of sale supplied at the time of order acknowledgment.
  TI warrants performance of its components to the specifications applicable at the time of sale, in accordance with the warranty in TI’s terms and conditions of sale of semiconductor products.
  Testing and other quality control techniques for TI components are used to the extent TI deems necessary to support this warranty. Except where mandated by applicable law,
  testing of all parameters of each component is not necessarily performed.
  TI assumes no liability for applications assistance or the design of Buyers’ products. Buyers are responsible for their products and applications using TI components. To minimize the risks
  associated with Buyers’ products and applications, Buyers should provide adequate design and operating safeguards.
  Reproduction of significant portions of TI information in TI data books, data sheets or reference designs is permissible only if reproduction is without alteration and is accompanied by all associated
  warranties, conditions, limitations, and notices. TI is not responsible or liable for such altered documentation. Information of third parties may be subject to additional restrictions.
  Buyer acknowledges and agrees that it is solely responsible for compliance with all legal, regulatory and safety-related requirements concerning its products, and any use of TI components in its
  applications, notwithstanding any applications-related information or support that may be provided by TI. Buyer represents and agrees that it has all the necessary expertise to create
  and implement safeguards that anticipate dangerous failures, monitor failures and their consequences, lessen the likelihood of dangerous failures and take appropriate remedial actions.
  Buyer will fully indemnify TI and its representatives against any damages arising out of the use of any TI components in Buyer’s safety-critical applications.
  In some cases, TI components may be promoted specifically to facilitate safety-related applications. With such components, TI’s goal is to help enable customers to design and create their own
  end-product solutions that meet applicable functional safety standards and requirements. Nonetheless, such components are subject to these terms.
  No TI components are authorized for use in FDA Class III (or similar life-critical medical equipment) unless authorized officers of the parties have executed an agreement specifically governing such use.
  Only those TI components that TI has specifically designated as military grade or “enhanced plastic” are designed and intended for use in military/aerospace applications or environments. Buyer
  acknowledges and agrees that any military or aerospace use of TI components that have not been so designated is solely at Buyer's risk, and Buyer is solely responsible for compliance with all
  legal and regulatory requirements in connection with such use.
  TI has specifically designated certain components as meeting ISO/TS16949 requirements, mainly for automotive use. In any case of use of non-designated products, TI will not be responsible for any
  failure to meet ISO/TS16949.
- TI Confidential
           NDA Restrictions
  Property of Texas Instruments Only
sheet 2
- 3.3V to 1.8V @250mA LDO
  for controller 1.8V analog
- 12V to 3V @500mA
  for FPGA Vccio
- 3.3V to 2.5V @150mA LDO
  for FPGA 2.5V AUX/PLL power
- Distribute ground vias around PCB
- 3.3V to 1.8V @1A LDO
  for HDMI Rx 1.8V analog
- Power Generation FPGA's VCCIO, 1.8V & 2.5V LDOs
sheet 3
- MSEL 4:0
  10011 = active serial standard POR
  10010 = active serial fast POR
- D
- FDV303N
- G
- S
- Use Altera's "Serial loader" option to update flash
  thru the FPGA JTAG port with Byteblaster cable
- Altera's USB ByteBlaster Connector
- FPGA Configuration
sheet 4
- FPGA Bank 5A, 5B, 7A, 8A
sheet 5
- JTAG pins are powered
  by Vccpd of Bank 3A
- FPGA Bank 2A, 3A, 3B, 4A
sheet 6
- 12V to 1.12V @6A
  Switching Freq ~ 700KHz
  Vstart/stop ~ 6.08V/5.57V
  SS ~ 3.5ms
- 12V to 1.8V @3A
  Switching Freq ~ 750KHz
  Vstart/stop ~ 8.44V/7.95V
  SS ~ 15ms
- 12V to 3.3V @5A
  Switching Freq ~ 750KHz
  Vstart/stop ~ 8.44V/7.95V
  SS ~ 15ms
- Power Generation 1.1V, 1.8V and 3.3V
sheet 7
- TI's EVM reference design has flex's
  electrical contact located  on the
  PCB's top (component) side
- Master DMD Flex
- Slave DMD Flex
- DMD Master/Slave Flex Connector
sheet 8
- Tied open drain outputs together
- Refer to the DLPC900 datasheet
  for other memory configurations.
- Slave Controller Flash Interface
